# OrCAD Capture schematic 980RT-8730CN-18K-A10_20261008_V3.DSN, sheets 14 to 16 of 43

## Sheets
14 P0041_S4_DUT1: size Custom
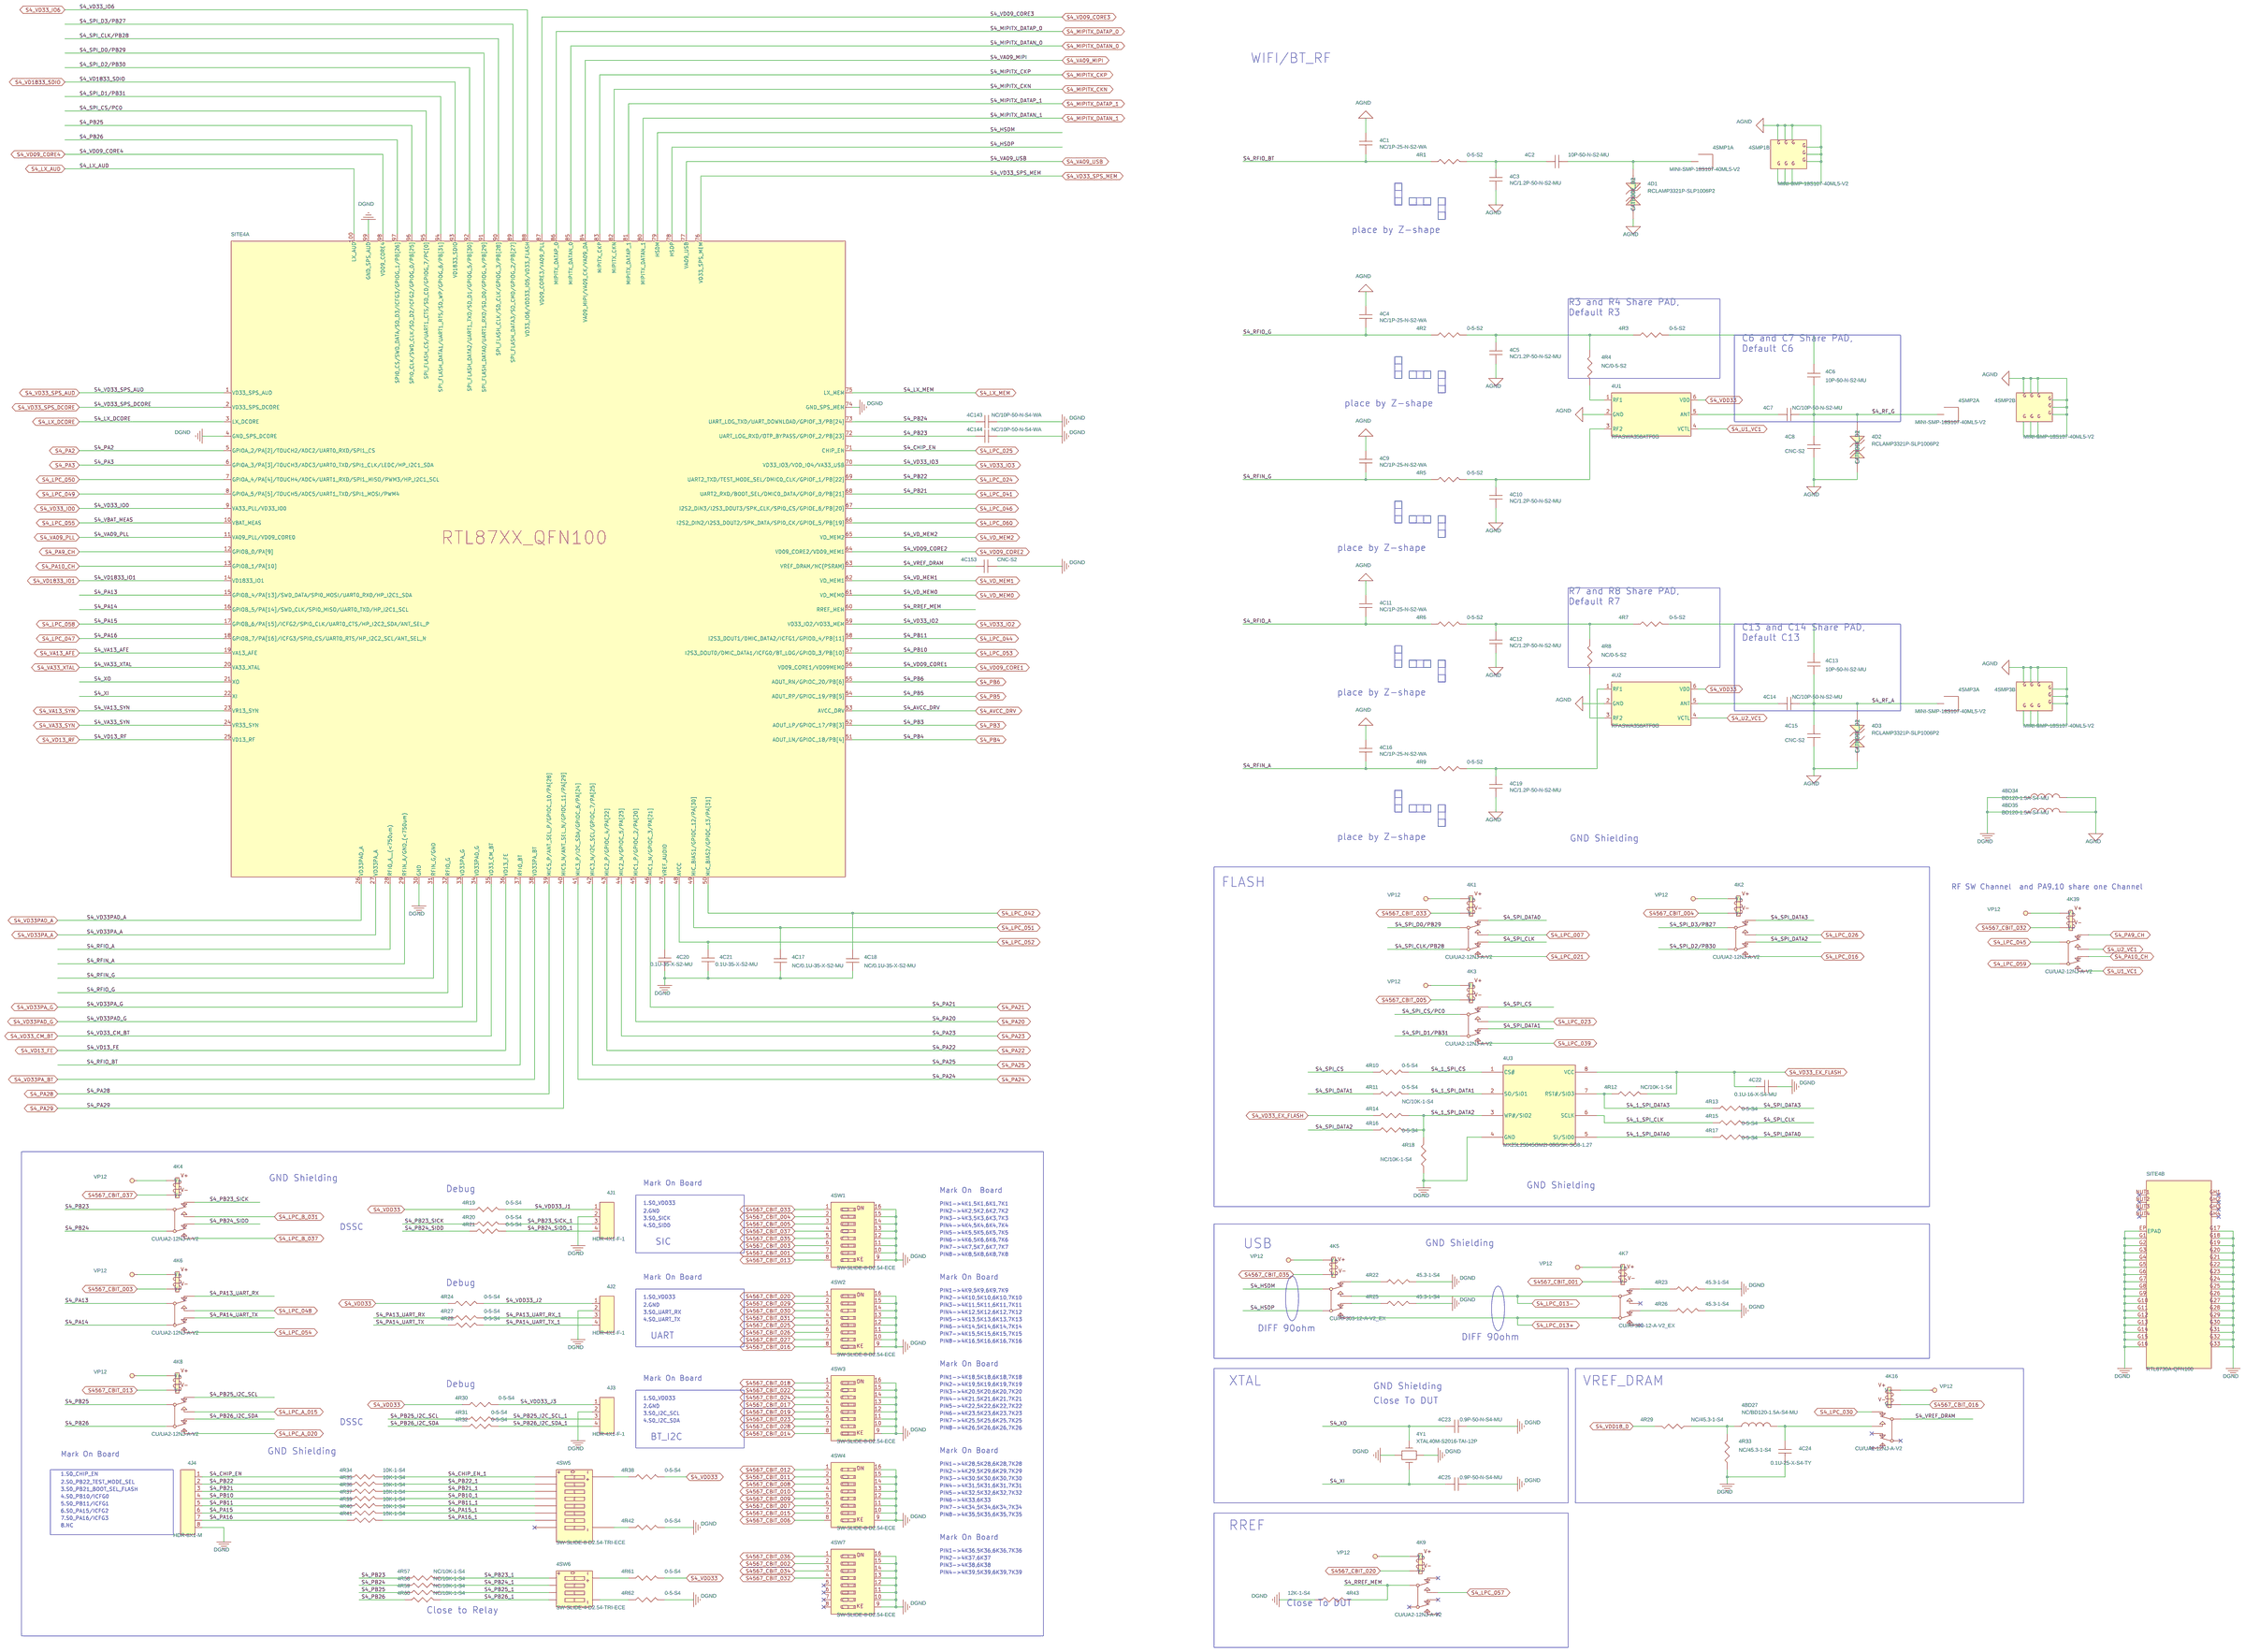
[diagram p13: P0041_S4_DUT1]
15 P0042_S4_Function-test: size A3
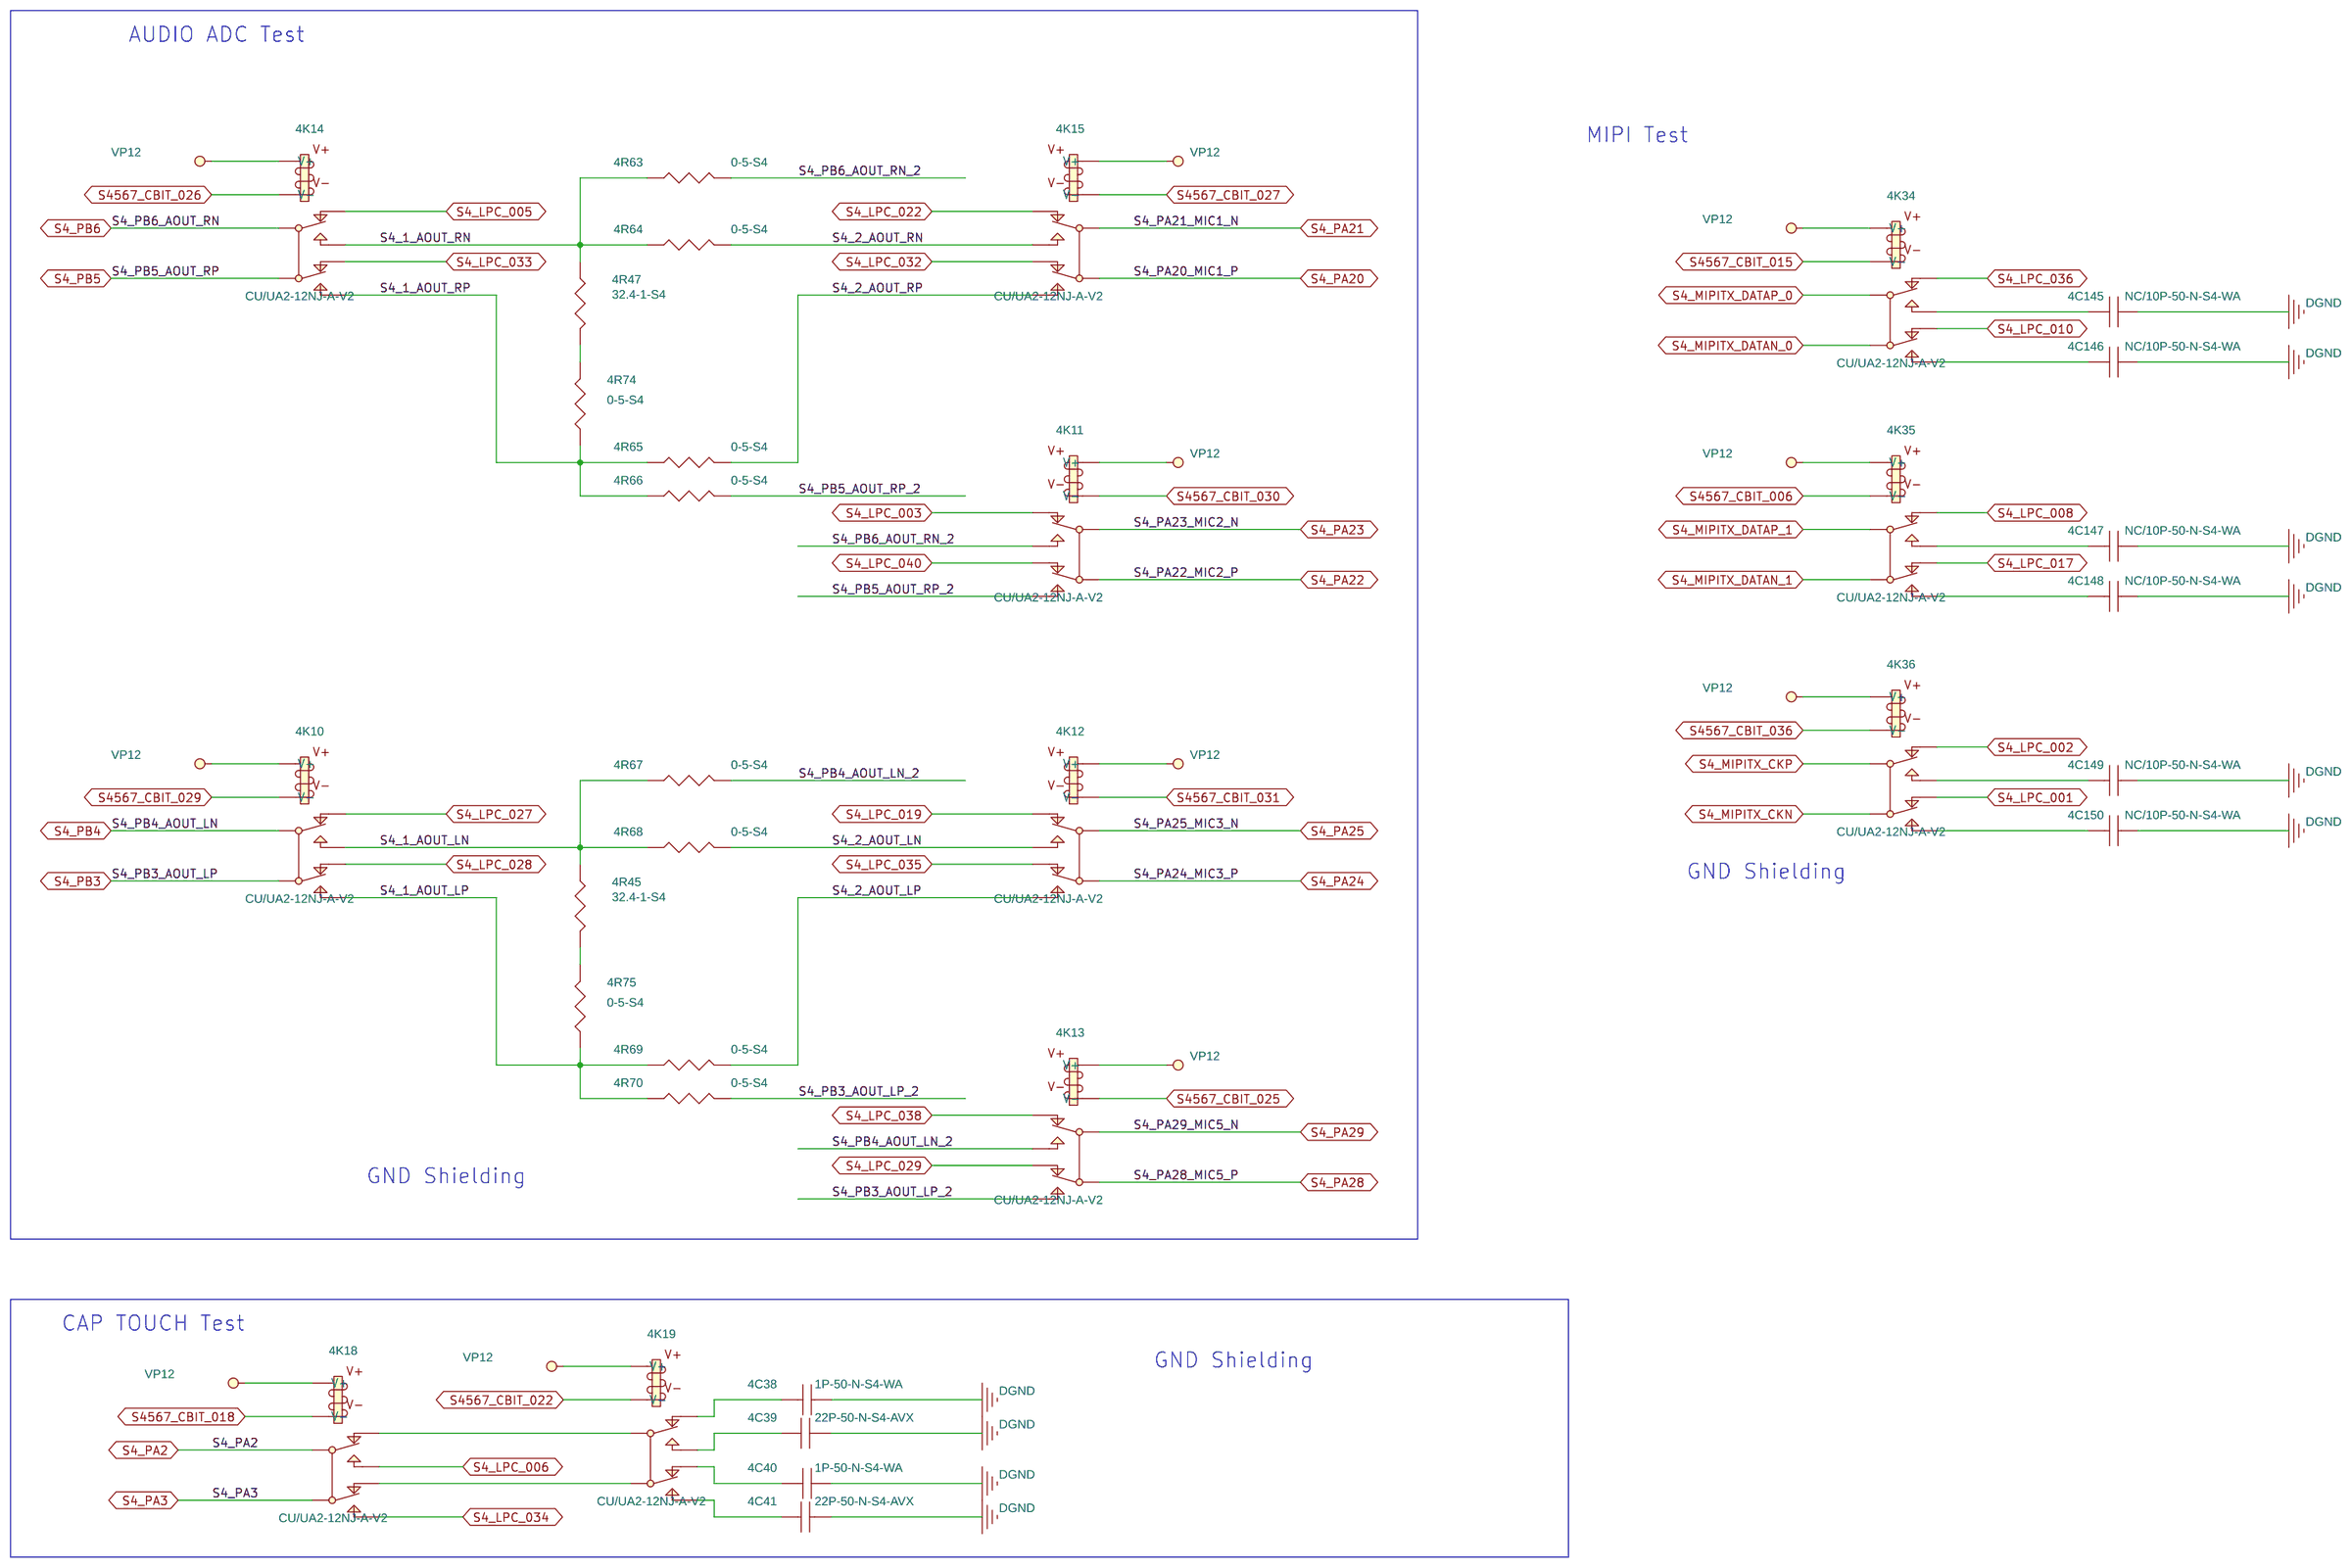
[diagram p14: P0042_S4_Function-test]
16 P0043_S4_Power: size A1
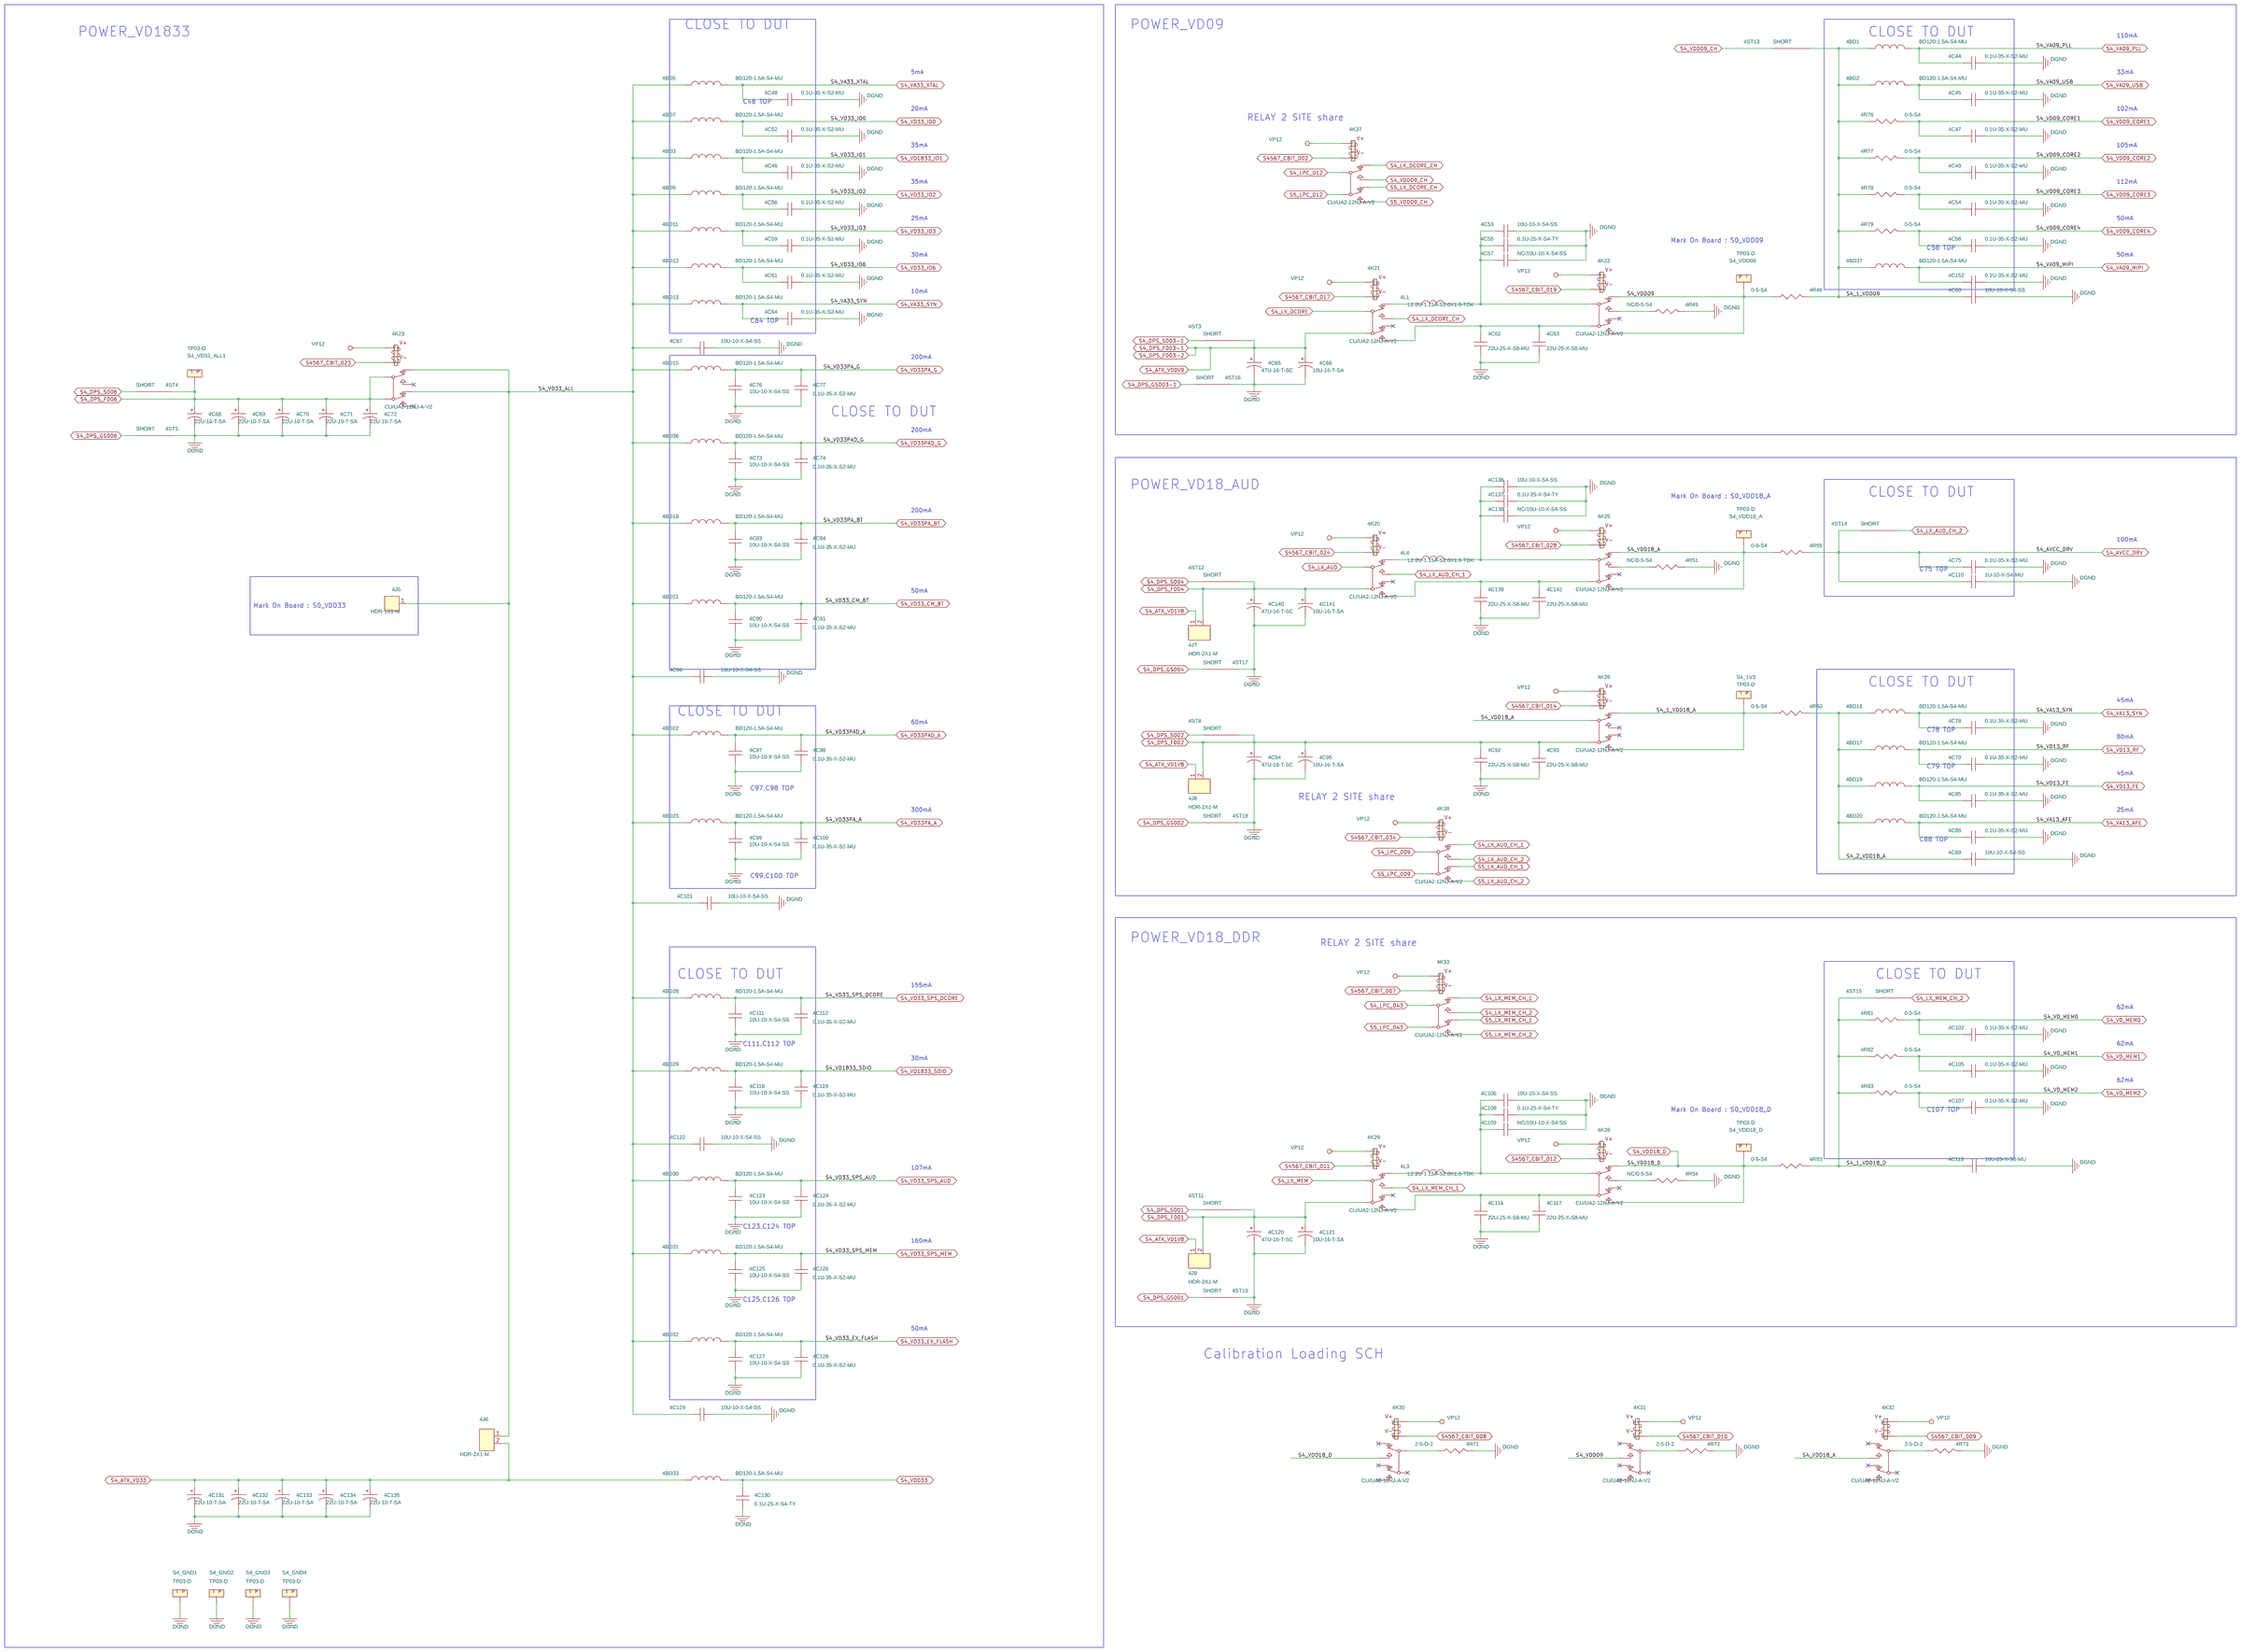
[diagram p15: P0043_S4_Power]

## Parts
sheet P0041_S4_DUT1
4BD27  NC/BD120-1.5A-S4-MU  [FB0402]
4BD34  BD120-1.5A-S4-MU  [FB0402]
4BD35  BD120-1.5A-S4-MU  [FB0402]
4C1  NC/1P-25-N-S2-WA  [C0201]
4C2  10P-50-N-S2-MU  [C0201]
4C3  NC/1.2P-50-N-S2-MU  [C0201]
4C4  NC/1P-25-N-S2-WA  [C0201]
4C5  NC/1.2P-50-N-S2-MU  [C0201]
4C6  10P-50-N-S2-MU  [C0201]
4C7  NC/10P-50-N-S2-MU  [C0201]
4C8  CNC-S2  [C0201]
4C9  NC/1P-25-N-S2-WA  [C0201]
4C10  NC/1.2P-50-N-S2-MU  [C0201]
4C11  NC/1P-25-N-S2-WA  [C0201]
4C12  NC/1.2P-50-N-S2-MU  [C0201]
4C13  10P-50-N-S2-MU  [C0201]
4C14  NC/10P-50-N-S2-MU  [C0201]
4C15  CNC-S2  [C0201]
4C16  NC/1P-25-N-S2-WA  [C0201]
4C17  NC/0.1U-35-X-S2-MU  [C0201]
4C18  NC/0.1U-35-X-S2-MU  [C0201]
4C19  NC/1.2P-50-N-S2-MU  [C0201]
4C20  0.1U-35-X-S2-MU  [C0201]
4C21  0.1U-35-X-S2-MU  [C0201]
4C22  0.1U-16-X-S4-MU  [C0402]
4C23  0.9P-50-N-S4-MU  [C0402]
4C24  0.1U-25-X-S4-TY  [C0402]
4C25  0.9P-50-N-S4-MU  [C0402]
4C143  NC/10P-50-N-S4-WA  [C0402]
4C144  NC/10P-50-N-S4-WA  [C0402]
4C153  CNC-S2  [C0201]
4D1  RCLAMP3321P-SLP1006P2  [DIODE_1X0P6MM]
4D2  RCLAMP3321P-SLP1006P2  [DIODE_1X0P6MM]
4D3  RCLAMP3321P-SLP1006P2  [DIODE_1X0P6MM]
4J1  HDR-4X1-F-1  [CONN_4X1_2P54MM_FL10P5MM]
4J2  HDR-4X1-F-1  [CONN_4X1_2P54MM_FL10P5MM]
4J3  HDR-4X1-F-1  [CONN_4X1_2P54MM_FL10P5MM]
4J4  HDR-8X1-M  [JP_8P_100]
4K1  CU/UA2-12NJ-A-V2  [RL_NECUA2_12V_V2]
4K2  CU/UA2-12NJ-A-V2  [RL_NECUA2_12V_V2]
4K3  CU/UA2-12NJ-A-V2  [RL_NECUA2_12V_V2]
4K4  CU/UA2-12NJ-A-V2  [RL_NECUA2_12V_V2]
4K5  CU/RF303-12-A-V2_EX  [RL_RF303_12V_V2]
4K6  CU/UA2-12NJ-A-V2  [RL_NECUA2_12V_V2]
4K7  CU/RF303-12-A-V2_EX  [RL_RF303_12V_V2]
4K8  CU/UA2-12NJ-A-V2  [RL_NECUA2_12V_V2]
4K9  CU/UA2-12NJ-A-V2  [RL_NECUA2_12V_V2]
4K16  CU/UA2-12NJ-A-V2  [RL_NECUA2_12V_V2]
4K39  CU/UA2-12NJ-A-V2  [RL_NECUA2_12V_V2]
4R1  0-5-S2  [R0201]
4R2  0-5-S2  [R0201]
4R3  0-5-S2  [R0201]
4R4  NC/0-5-S2  [R0201]
4R5  0-5-S2  [R0201]
4R6  0-5-S2  [R0201]
4R7  0-5-S2  [R0201]
4R8  NC/0-5-S2  [R0201]
4R9  0-5-S2  [R0201]
4R10  0-5-S4  [R0402]
4R11  0-5-S4  [R0402]
4R12  NC/10K-1-S4  [R0402]
4R13  0-5-S4  [R0402]
4R14  NC/10K-1-S4  [R0402]
4R15  0-5-S4  [R0402]
4R16  0-5-S4  [R0402]
4R17  0-5-S4  [R0402]
4R18  NC/10K-1-S4  [R0402]
4R19  0-5-S4  [R0402]
4R20  0-5-S4  [R0402]
4R21  0-5-S4  [R0402]
4R22  45.3-1-S4  [R0402]
4R23  45.3-1-S4  [R0402]
4R24  0-5-S4  [R0402]
4R25  45.3-1-S4  [R0402]
4R26  45.3-1-S4  [R0402]
4R27  0-5-S4  [R0402]
4R28  0-5-S4  [R0402]
4R29  NC/45.3-1-S4  [R0402]
4R30  0-5-S4  [R0402]
4R31  0-5-S4  [R0402]
4R32  0-5-S4  [R0402]
4R33  NC/45.3-1-S4  [R0402]
4R34  10K-1-S4  [R0402]
4R35  10K-1-S4  [R0402]
4R36  10K-1-S4  [R0402]
4R37  10K-1-S4  [R0402]
4R38  0-5-S4  [R0402]
4R39  10K-1-S4  [R0402]
4R40  10K-1-S4  [R0402]
4R41  10K-1-S4  [R0402]
4R42  0-5-S4  [R0402]
4R43  12K-1-S4  [R0402]
4R57  NC/10K-1-S4  [R0402]
4R58  NC/10K-1-S4  [R0402]
4R59  NC/10K-1-S4  [R0402]
4R60  NC/10K-1-S4  [R0402]
4R61  0-5-S4  [R0402]
4R62  0-5-S4  [R0402]
4SMP1  MINI-SMP-18S107-40ML5-V2  [CONN_SMP_18S107]  (sections A,B)
4SMP2  MINI-SMP-18S107-40ML5-V2  [CONN_SMP_18S107]  (sections A,B)
4SMP3  MINI-SMP-18S107-40ML5-V2  [CONN_SMP_18S107]  (sections A,B)
4SW1  SW-SLIDE-8-D2.54-ECE  [SW_DIPX8_16P_H5MM]
4SW2  SW-SLIDE-8-D2.54-ECE  [SW_DIPX8_16P_H5MM]
4SW3  SW-SLIDE-8-D2.54-ECE  [SW_DIPX8_16P_H5MM]
4SW4  SW-SLIDE-8-D2.54-ECE  [SW_DIPX8_16P_H5MM]
4SW5  SW-SLIDE-8-D2.54-TRI-ECE  [SW_DIPX8P_2P54_MM_V2]
4SW6  SW-SLIDE-4-D2.54-TRI-ECE  [SW_DIPX4P_2P54MM_ETD]
4SW7  SW-SLIDE-8-D2.54-ECE  [SW_DIPX8_16P_H5MM]
4U1  RFASWA358ATF0G  [RF_SW_GW2159_6P]
4U2  RFASWA358ATF0G  [RF_SW_GW2159_6P]
4U3  MX25L25645GM2I-08G/SK-SO8-1.27  [SK_SO8_1P27MM_LOTES]
4Y1  XTAL40M-S2016-TAI-12P  [XTAL_2X1P6MM_4P_0P8MM]
SITE4  RTL8730A-QFN100  [SK_QFN100P_0P35MM_MJC_L8730A]  (sections A,B)
sheet P0042_S4_Function-test
4C38  1P-50-N-S4-WA  [C0402]
4C39  22P-50-N-S4-AVX  [C0402]
4C40  1P-50-N-S4-WA  [C0402]
4C41  22P-50-N-S4-AVX  [C0402]
4C145  NC/10P-50-N-S4-WA  [C0402]
4C146  NC/10P-50-N-S4-WA  [C0402]
4C147  NC/10P-50-N-S4-WA  [C0402]
4C148  NC/10P-50-N-S4-WA  [C0402]
4C149  NC/10P-50-N-S4-WA  [C0402]
4C150  NC/10P-50-N-S4-WA  [C0402]
4K10  CU/UA2-12NJ-A-V2  [RL_NECUA2_12V_V2]
4K11  CU/UA2-12NJ-A-V2  [RL_NECUA2_12V_V2]
4K12  CU/UA2-12NJ-A-V2  [RL_NECUA2_12V_V2]
4K13  CU/UA2-12NJ-A-V2  [RL_NECUA2_12V_V2]
4K14  CU/UA2-12NJ-A-V2  [RL_NECUA2_12V_V2]
4K15  CU/UA2-12NJ-A-V2  [RL_NECUA2_12V_V2]
4K18  CU/UA2-12NJ-A-V2  [RL_NECUA2_12V_V2]
4K19  CU/UA2-12NJ-A-V2  [RL_NECUA2_12V_V2]
4K34  CU/UA2-12NJ-A-V2  [RL_NECUA2_12V_V2]
4K35  CU/UA2-12NJ-A-V2  [RL_NECUA2_12V_V2]
4K36  CU/UA2-12NJ-A-V2  [RL_NECUA2_12V_V2]
4R45  32.4-1-S4  [R0402]
4R47  32.4-1-S4  [R0402]
4R63  0-5-S4  [R0402]
4R64  0-5-S4  [R0402]
4R65  0-5-S4  [R0402]
4R66  0-5-S4  [R0402]
4R67  0-5-S4  [R0402]
4R68  0-5-S4  [R0402]
4R69  0-5-S4  [R0402]
4R70  0-5-S4  [R0402]
4R74  0-5-S4  [R0402]
4R75  0-5-S4  [R0402]
sheet P0043_S4_Power
4BD1  BD120-1.5A-S4-MU  [FB0402]
4BD2  BD120-1.5A-S4-MU  [FB0402]
4BD3  BD120-1.5A-S4-MU  [FB0402]
4BD5  BD120-1.5A-S4-MU  [FB0402]
4BD7  BD120-1.5A-S4-MU  [FB0402]
4BD9  BD120-1.5A-S4-MU  [FB0402]
4BD11  BD120-1.5A-S4-MU  [FB0402]
4BD12  BD120-1.5A-S4-MU  [FB0402]
4BD13  BD120-1.5A-S4-MU  [FB0402]
4BD15  BD120-1.5A-S4-MU  [FB0402]
4BD16  BD120-1.5A-S4-MU  [FB0402]
4BD17  BD120-1.5A-S4-MU  [FB0402]
4BD18  BD120-1.5A-S4-MU  [FB0402]
4BD19  BD120-1.5A-S4-MU  [FB0402]
4BD20  BD120-1.5A-S4-MU  [FB0402]
4BD21  BD120-1.5A-S4-MU  [FB0402]
4BD22  BD120-1.5A-S4-MU  [FB0402]
4BD23  BD120-1.5A-S4-MU  [FB0402]
4BD28  BD120-1.5A-S4-MU  [FB0402]
4BD29  BD120-1.5A-S4-MU  [FB0402]
4BD30  BD120-1.5A-S4-MU  [FB0402]
4BD31  BD120-1.5A-S4-MU  [FB0402]
4BD32  BD120-1.5A-S4-MU  [FB0402]
4BD33  BD120-1.5A-S4-MU  [FB0402]
4BD36  BD120-1.5A-S4-MU  [FB0402]
4BD37  BD120-1.5A-S4-MU  [FB0402]
4C44  0.1U-35-X-S2-MU  [C0201]
4C45  0.1U-35-X-S2-MU  [C0201]
4C46  0.1U-35-X-S2-MU  [C0201]
4C47  0.1U-35-X-S2-MU  [C0201]
4C48  0.1U-35-X-S2-MU  [C0201]
4C49  0.1U-35-X-S2-MU  [C0201]
4C52  0.1U-35-X-S2-MU  [C0201]
4C53  10U-10-X-S4-SS  [C0402]
4C54  0.1U-35-X-S2-MU  [C0201]
4C55  0.1U-25-X-S4-TY  [C0402]
4C56  0.1U-35-X-S2-MU  [C0201]
4C57  NC/10U-10-X-S4-SS  [C0402]
4C58  0.1U-35-X-S2-MU  [C0201]
4C59  0.1U-35-X-S2-MU  [C0201]
4C60  10U-10-X-S4-SS  [C0402]
4C61  0.1U-35-X-S2-MU  [C0201]
4C62  22U-25-X-S8-MU  [C0805]
4C63  22U-25-X-S8-MU  [C0805]
4C64  0.1U-35-X-S2-MU  [C0201]
4C65  47U-16-T-SC  [CODE_C]
4C66  10U-16-T-SA  [CODE_A]
4C67  10U-10-X-S4-SS  [C0402]
4C68  22U-10-T-SA  [CODE_A]
4C69  22U-10-T-SA  [CODE_A]
4C70  22U-10-T-SA  [CODE_A]
4C71  22U-10-T-SA  [CODE_A]
4C72  22U-10-T-SA  [CODE_A]
4C73  10U-10-X-S4-SS  [C0402]
4C74  0.1U-35-X-S2-MU  [C0201]
4C75  0.1U-35-X-S2-MU  [C0201]
4C76  10U-10-X-S4-SS  [C0402]
4C77  0.1U-35-X-S2-MU  [C0201]
4C78  0.1U-35-X-S2-MU  [C0201]
4C79  0.1U-35-X-S2-MU  [C0201]
4C83  10U-10-X-S4-SS  [C0402]
4C84  0.1U-35-X-S2-MU  [C0201]
4C85  0.1U-35-X-S2-MU  [C0201]
4C88  0.1U-35-X-S2-MU  [C0201]
4C89  10U-10-X-S4-SS  [C0402]
4C90  10U-10-X-S4-SS  [C0402]
4C91  0.1U-35-X-S2-MU  [C0201]
4C92  22U-25-X-S8-MU  [C0805]
4C93  22U-25-X-S8-MU  [C0805]
4C94  47U-16-T-SC  [CODE_C]
4C95  10U-16-T-SA  [CODE_A]
4C96  10U-10-X-S4-SS  [C0402]
4C97  10U-10-X-S4-SS  [C0402]
4C98  0.1U-35-X-S2-MU  [C0201]
4C99  10U-10-X-S4-SS  [C0402]
4C100  0.1U-35-X-S2-MU  [C0201]
4C101  10U-10-X-S4-SS  [C0402]
4C102  0.1U-35-X-S2-MU  [C0201]
4C105  0.1U-35-X-S2-MU  [C0201]
4C106  10U-10-X-S4-SS  [C0402]
4C107  0.1U-35-X-S2-MU  [C0201]
4C108  0.1U-25-X-S4-TY  [C0402]
4C109  NC/10U-10-X-S4-SS  [C0402]
4C110  1U-10-X-S4-MU  [C0402]
4C111  10U-10-X-S4-SS  [C0402]
4C112  0.1U-35-X-S2-MU  [C0201]
4C113  10U-25-X-S6-MU  [C0603]
4C116  22U-25-X-S8-MU  [C0805]
4C117  22U-25-X-S8-MU  [C0805]
4C118  10U-10-X-S4-SS  [C0402]
4C119  0.1U-35-X-S2-MU  [C0201]
4C120  47U-16-T-SC  [CODE_C]
4C121  10U-16-T-SA  [CODE_A]
4C122  10U-10-X-S4-SS  [C0402]
4C123  10U-10-X-S4-SS  [C0402]
4C124  0.1U-35-X-S2-MU  [C0201]
4C125  10U-10-X-S4-SS  [C0402]
4C126  0.1U-35-X-S2-MU  [C0201]
4C127  10U-10-X-S4-SS  [C0402]
4C128  0.1U-35-X-S2-MU  [C0201]
4C129  10U-10-X-S4-SS  [C0402]
4C130  0.1U-25-X-S4-TY  [C0402]
4C131  22U-10-T-SA  [CODE_A]
4C132  22U-10-T-SA  [CODE_A]
4C133  22U-10-T-SA  [CODE_A]
4C134  22U-10-T-SA  [CODE_A]
4C135  22U-10-T-SA  [CODE_A]
4C136  10U-10-X-S4-SS  [C0402]
4C137  0.1U-25-X-S4-TY  [C0402]
4C138  NC/10U-10-X-S4-SS  [C0402]
4C139  22U-25-X-S8-MU  [C0805]
4C140  47U-16-T-SC  [CODE_C]
4C141  10U-16-T-SA  [CODE_A]
4C142  22U-25-X-S8-MU  [C0805]
4C152  0.1U-35-X-S2-MU  [C0201]
4J5  HDR-1X1-M  [JP_1P_RD070_040]
4J6  HDR-2X1-M  [JP_2P_100]
4J7  HDR-2X1-M  [JP_2P_100]
4J8  HDR-2X1-M  [JP_2P_100]
4J9  HDR-2X1-M  [JP_2P_100]
4K20  CU/UA2-12NJ-A-V2  [RL_NECUA2_12V_V2]
4K21  CU/UA2-12NJ-A-V2  [RL_NECUA2_12V_V2]
4K22  CU/UA2-12NJ-A-V2  [RL_NECUA2_12V_V2]
4K23  CU/UA2-12NJ-A-V2  [RL_NECUA2_12V_V2]
4K25  CU/UA2-12NJ-A-V2  [RL_NECUA2_12V_V2]
4K26  CU/UA2-12NJ-A-V2  [RL_NECUA2_12V_V2]
4K28  CU/UA2-12NJ-A-V2  [RL_NECUA2_12V_V2]
4K29  CU/UA2-12NJ-A-V2  [RL_NECUA2_12V_V2]
4K30  CU/UA2-12NJ-A-V2  [RL_NECUA2_12V_V2]
4K31  CU/UA2-12NJ-A-V2  [RL_NECUA2_12V_V2]
4K32  CU/UA2-12NJ-A-V2  [RL_NECUA2_12V_V2]
4K33  CU/UA2-12NJ-A-V2  [RL_NECUA2_12V_V2]
4K37  CU/UA2-12NJ-A-V2  [RL_NECUA2_12V_V2]
4K38  CU/UA2-12NJ-A-V2  [RL_NECUA2_12V_V2]
4L1  L2.2U-1.15A-S2.0X1.6-TDK  [IND_VL252012E]
4L3  L2.2U-1.15A-S2.0X1.6-TDK  [IND_VL252012E]
4L4  L2.2U-1.15A-S2.0X1.6-TDK  [IND_VL252012E]
4R48  0-5-S4  [R0402]
4R49  NC/0-5-S4  [R0402]
4R50  0-5-S4  [R0402]
4R51  NC/0-5-S4  [R0402]
4R53  0-5-S4  [R0402]
4R54  NC/0-5-S4  [R0402]
4R55  0-5-S4  [R0402]
4R71  2-5-D-2  [RC02W_27MM]
4R72  2-5-D-2  [RC02W_27MM]
4R73  2-5-D-2  [RC02W_27MM]
4R76  0-5-S4  [R0402]
4R77  0-5-S4  [R0402]
4R78  0-5-S4  [R0402]
4R79  0-5-S4  [R0402]
4R81  0-5-S4  [R0402]
4R82  0-5-S4  [R0402]
4R83  0-5-S4  [R0402]
4ST3  SHORT  [DEFAULT_SHORT_SMALL]
4ST4  SHORT  [DEFAULT_SHORT_SMALL]
4ST5  SHORT  [DEFAULT_SHORT_SMALL]
4ST8  SHORT  [DEFAULT_SHORT_SMALL]
4ST11  SHORT  [DEFAULT_SHORT_SMALL]
4ST12  SHORT  [DEFAULT_SHORT_SMALL]
4ST13  SHORT  [DEFAULT_SHORT_SMALL]
4ST14  SHORT  [DEFAULT_SHORT_SMALL]
4ST15  SHORT  [DEFAULT_SHORT_SMALL]
4ST16  SHORT  [DEFAULT_SHORT_SMALL]
4ST17  SHORT  [DEFAULT_SHORT_SMALL]
4ST18  SHORT  [DEFAULT_SHORT_SMALL]
4ST19  SHORT  [DEFAULT_SHORT_SMALL]
S4_1V3  TP03-D  [TP_060_040]
S4_GND1  TP03-D  [TP_060_040]
S4_GND2  TP03-D  [TP_060_040]
S4_GND3  TP03-D  [TP_060_040]
S4_GND4  TP03-D  [TP_060_040]
S4_VD33_ALL1  TP03-D  [TP_060_040]
S4_VDD09  TP03-D  [TP_060_040]
S4_VDD18_A  TP03-D  [TP_060_040]
S4_VDD18_D  TP03-D  [TP_060_040]

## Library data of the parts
4BD27 = BD120-1.5A-S4-MU: KAIROSNAME: BD27
4BD34 = BD120-1.5A-S4-MU: KAIROSNAME: BD34
4BD35 = BD120-1.5A-S4-MU: KAIROSNAME: BD35
4C1 4C4 4C9 4C11 4C16 = 1P-25-N-S2-WA
4C2 4C6 4C7 4C13 4C14 = 10P-50-N-S2-MU
4C3 4C5 4C10 4C12 4C19 = 1.2P-50-N-S2-MU
4C8 4C15 = CNC-S4
4C17 4C18 4C46 = 0.1U-35-X-S2-MU: KAIROSNAME: C46
4C20 4C21 4C98 = 0.1U-35-X-S2-MU: KAIROSNAME: C98
4C22 = 0.1U-16-X-S4: KAIROSNAME: C22
4C23 = 10P-50-N-S4-MU-1: KAIROSNAME: C23
4C24 = 0.1U-25-X-S4-TY: KAIROSNAME: C24
4C25 = 10P-50-N-S4-MU-1: KAIROSNAME: C25
4C143-4C150 = 10P-50-N-S4-WA
4C48 4C153 = 0.1U-35-X-S2-MU: KAIROSNAME: C48
4D1 = RCLAMP3321P-SLP1006P2: KAIROSNAME: D1
4D2 = RCLAMP3321P-SLP1006P2: KAIROSNAME: D2
4D3 = RCLAMP3321P-SLP1006P2: KAIROSNAME: D3
4J1-4J3 = HDR-4X1-F-1
4J4 = HDR-8X1-M: KAIROSNAME: J4
4K1 4K39 = CU_UA2-12NJ-A-V2: KAIROSNAME: K1
4K2 4K16 = CU_UA2-12NJ-A-V2: KAIROSNAME: K2
4K3 = CU_UA2-12NJ-A-V2: KAIROSNAME: K3
4K4 = CU_UA2-12NJ-A-V2: KAIROSNAME: K4
4K5 = CU_RF303-12-A-V2_EX: KAIROSNAME: K5
4K6 = CU_UA2-12NJ-A-V2: KAIROSNAME: K6
4K7 = CU_RF303-12-A-V2_EX: KAIROSNAME: K7
4K8 = CU_UA2-12NJ-A-V2: KAIROSNAME: K8
4K9 = CU_UA2-12NJ-A-V2: KAIROSNAME: K9
4R1-4R9 = 0-5-S2
4R10 = 0-5-S4: KAIROSNAME: R10
4R11 = 0-5-S4: KAIROSNAME: R11
4R12 = 10K-1-S4: KAIROSNAME: R12
4R13 = 0-5-S4: KAIROSNAME: R13
4R14 = 10K-1-S4: KAIROSNAME: R14
4R15 = 0-5-S4: KAIROSNAME: R15
4R16 = 0-5-S4: KAIROSNAME: R16
4R17 = 0-5-S4: KAIROSNAME: R17
4R18 = 10K-1-S4: KAIROSNAME: R18
4R19 = 0-5-S4: KAIROSNAME: R19
4R20 = 0-5-S4: KAIROSNAME: R20
4R21 = 0-5-S4: KAIROSNAME: R21
4R22 = 45.3-1-S4: KAIROSNAME: R22
4R23 = 45.3-1-S4: KAIROSNAME: R23
4R24 = 0-5-S4: KAIROSNAME: R24
4R25 = 45.3-1-S4: KAIROSNAME: R25
4R26 = 45.3-1-S4: KAIROSNAME: R26
4R27 = 0-5-S4: KAIROSNAME: R27
4R28 = 0-5-S4: KAIROSNAME: R28
4R29 = 45.3-1-S4: KAIROSNAME: R29
4R30 = 0-5-S4: KAIROSNAME: R30
4R31 = 0-5-S4: KAIROSNAME: R31
4R32 = 0-5-S4: KAIROSNAME: R32
4R33 = 45.3-1-S4: KAIROSNAME: R33
4R34 = 10K-1-S4: KAIROSNAME: R34
4R35 = 10K-1-S4: KAIROSNAME: R35
4R36 = 10K-1-S4: KAIROSNAME: R36
4R37 = 10K-1-S4: KAIROSNAME: R37
4R38 = 0-5-S4: KAIROSNAME: R38
4R39 = 10K-1-S4: KAIROSNAME: R39
4R40 = 10K-1-S4: KAIROSNAME: R40
4R41 = 10K-1-S4: KAIROSNAME: R41
4R42 = 0-5-S4: KAIROSNAME: R42
4R43 = 12K-1-S4: KAIROSNAME: R43
4R57 = 10K-1-S4: KAIROSNAME: R57
4R58 = 10K-1-S4: KAIROSNAME: R58
4R59 = 10K-1-S4: KAIROSNAME: R59
4R60 = 10K-1-S4: KAIROSNAME: R60
4R61 = 0-5-S4: KAIROSNAME: R61
4R62 = 0-5-S4: KAIROSNAME: R62
4SMP1 = MINI-SMP-18S107-40ML5-V2: KAIROSNAME: SMP1A
4SMP2 = MINI-SMP-18S107-40ML5-V2: KAIROSNAME: SMP2A
4SMP3 = MINI-SMP-18S107-40ML5-V2: KAIROSNAME: SMP3A
4SW1-4SW4 4SW7 = SW-SLIDE-8-D2.54-ECE
4SW5 = SW-SLIDE-8-D2.54-TRI-ECE
4SW6 = SW-SLIDE-4-D2.54-TRI-ECE
4U1 4U2 = RFASWA358ATF0G
4U3 = MX25R6435FM2IL0-SOP8: KAIROSNAME: U3
4Y1 = XTAL40M-S2016-TAI-12P: KAIROSNAME: Y1
SITE4 = RTL8730A-QFN100
4C38 = 10P-50-N-S4-MU-1: KAIROSNAME: C38
4C39 = 33P-50-N-S4-WA: KAIROSNAME: C39
4C40 = 10P-50-N-S4-MU-1: KAIROSNAME: C40
4C41 = 33P-50-N-S4-WA: KAIROSNAME: C41
4K10 = CU_UA2-12NJ-A-V2: KAIROSNAME: K10
4K11 = CU_UA2-12NJ-A-V2: KAIROSNAME: K11
4K12 = CU_UA2-12NJ-A-V2: KAIROSNAME: K12
4K13 = CU_UA2-12NJ-A-V2: KAIROSNAME: K13
4K14 = CU_UA2-12NJ-A-V2: KAIROSNAME: K14
4K15 4K34-4K36 = CU_UA2-12NJ-A-V2: KAIROSNAME: K15
4K18 = CU_UA2-12NJ-A-V2: KAIROSNAME: K18
4K19 = CU_UA2-12NJ-A-V2: KAIROSNAME: K19
4R45 = 32.4-1-S4: KAIROSNAME: R45
4R47 = 32.4-1-S4: KAIROSNAME: R47
4R63 = 0-5-S4: KAIROSNAME: R63
4R64 = 0-5-S4: KAIROSNAME: R64
4R65 4R74 4R75 = 0-5-S4: KAIROSNAME: R65
4R66 = 0-5-S4: KAIROSNAME: R66
4R67 = 0-5-S4: KAIROSNAME: R67
4R68 = 0-5-S4: KAIROSNAME: R68
4R69 = 0-5-S4: KAIROSNAME: R69
4R70 = 0-5-S4: KAIROSNAME: R70
4BD1 = BD120-1.5A-S4-MU: KAIROSNAME: BD1
4BD2 = BD120-1.5A-S4-MU: KAIROSNAME: BD2
4BD3 = BD120-1.5A-S4-MU: KAIROSNAME: BD3
4BD5 = BD120-1.5A-S4-MU: KAIROSNAME: BD5
4BD7 = BD120-1.5A-S4-MU: KAIROSNAME: BD7
4BD9 = BD120-1.5A-S4-MU: KAIROSNAME: BD9
4BD11 = BD120-1.5A-S4-MU: KAIROSNAME: BD11
4BD12 = BD120-1.5A-S4-MU: KAIROSNAME: BD12
4BD13 = BD120-1.5A-S4-MU: KAIROSNAME: BD13
4BD15 4BD36 = BD120-1.5A-S4-MU: KAIROSNAME: BD15
4BD16 = BD120-1.5A-S4-MU: KAIROSNAME: BD16
4BD17 = BD120-1.5A-S4-MU: KAIROSNAME: BD17
4BD18 = BD120-1.5A-S4-MU: KAIROSNAME: BD18
4BD19 = BD120-1.5A-S4-MU: KAIROSNAME: BD19
4BD20 = BD120-1.5A-S4-MU: KAIROSNAME: BD20
4BD21 = BD120-1.5A-S4-MU: KAIROSNAME: BD21
4BD22 = BD120-1.5A-S4-MU: KAIROSNAME: BD22
4BD23 = BD120-1.5A-S4-MU: KAIROSNAME: BD23
4BD28 = BD120-1.5A-S4-MU: KAIROSNAME: BD28
4BD29 = BD120-1.5A-S4-MU: KAIROSNAME: BD29
4BD30 = BD120-1.5A-S4-MU: KAIROSNAME: BD30
4BD31 = BD120-1.5A-S4-MU: KAIROSNAME: BD31
4BD32 = BD120-1.5A-S4-MU: KAIROSNAME: BD32
4BD33 = BD120-1.5A-S4-MU: KAIROSNAME: BD33
4BD37 = BD120-1.5A-S4-MU: KAIROSNAME: BD10
4C44 = 0.1U-35-X-S2-MU: KAIROSNAME: C44
4C45 = 0.1U-35-X-S2-MU: KAIROSNAME: C45
4C47 = 0.1U-35-X-S2-MU: KAIROSNAME: C47
4C49 = 0.1U-35-X-S2-MU: KAIROSNAME: C49
4C52 = 0.1U-35-X-S2-MU: KAIROSNAME: C52
4C53 = 10U-10-X-S4-SS: KAIROSNAME: C53
4C54 = 0.1U-35-X-S2-MU: KAIROSNAME: C54
4C55 = 0.1U-25-X-S4-TY: KAIROSNAME: C55
4C56 = 0.1U-35-X-S2-MU: KAIROSNAME: C56
4C57 = 10U-10-X-S4-SS: KAIROSNAME: C57
4C58 4C152 = 0.1U-35-X-S2-MU: KAIROSNAME: C58
4C59 = 0.1U-35-X-S2-MU: KAIROSNAME: C59
4C60 = 10U-10-X-S4-SS: KAIROSNAME: C60
4C61 = 0.1U-35-X-S2-MU: KAIROSNAME: C61
4C62 = 22U-25-X-S8-MU: KAIROSNAME: C62
4C63 = 22U-25-X-S8-MU: KAIROSNAME: C63
4C64 = 0.1U-35-X-S2-MU: KAIROSNAME: C64
4C65 = 47U-16-T-SC: KAIROSNAME: C65
4C66 = 10U-16-T-SA: KAIROSNAME: C66
4C67 = 10U-10-X-S4-SS: KAIROSNAME: C67
4C68 = 22U-10-T-SA: KAIROSNAME: C68
4C69 = 22U-10-T-SA: KAIROSNAME: C69
4C70 = 22U-10-T-SA: KAIROSNAME: C70
4C71 = 22U-10-T-SA: KAIROSNAME: C71
4C72 = 22U-10-T-SA: KAIROSNAME: C72
4C73 4C76 = 10U-10-X-S4-SS: KAIROSNAME: C76
4C74 4C77 = 0.1U-35-X-S2-MU: KAIROSNAME: C77
4C75 = 0.1U-35-X-S2-MU: KAIROSNAME: C75
4C78 = 0.1U-35-X-S2-MU: KAIROSNAME: C78
4C79 = 0.1U-35-X-S2-MU: KAIROSNAME: C79
4C83 = 10U-10-X-S4-SS: KAIROSNAME: C83
4C84 = 0.1U-35-X-S2-MU: KAIROSNAME: C84
4C85 = 0.1U-35-X-S2-MU: KAIROSNAME: C85
4C88 = 0.1U-35-X-S2-MU: KAIROSNAME: C88
4C89 = 10U-10-X-S4-SS: KAIROSNAME: C89
4C90 = 10U-10-X-S4-SS: KAIROSNAME: C90
4C91 = 0.1U-35-X-S2-MU: KAIROSNAME: C91
4C92 = 22U-25-X-S8-MU: KAIROSNAME: C92
4C93 = 22U-25-X-S8-MU: KAIROSNAME: C93
4C94 = 47U-16-T-SC: KAIROSNAME: C94
4C95 = 10U-16-T-SA: KAIROSNAME: C95
4C96 = 10U-10-X-S4-SS: KAIROSNAME: C96
4C97 = 10U-10-X-S4-SS: KAIROSNAME: C97
4C99 = 10U-10-X-S4-SS: KAIROSNAME: C99
4C100 = 0.1U-35-X-S2-MU: KAIROSNAME: C100
4C101 = 10U-10-X-S4-SS: KAIROSNAME: C101
4C102 = 0.1U-35-X-S2-MU: KAIROSNAME: C102
4C105 = 0.1U-35-X-S2-MU: KAIROSNAME: C105
4C106 = 10U-10-X-S4-SS: KAIROSNAME: C106
4C107 = 0.1U-35-X-S2-MU: KAIROSNAME: C107
4C108 = 0.1U-25-X-S4-TY: KAIROSNAME: C108
4C109 = 10U-10-X-S4-SS: KAIROSNAME: C109
4C110 = 10U-10-X-S4-SS: KAIROSNAME: C110
4C111 = 10U-10-X-S4-SS: KAIROSNAME: C111
4C112 = 0.1U-35-X-S2-MU: KAIROSNAME: C112
4C113 = 10U-25-X-S6-MU: KAIROSNAME: C113
4C116 = 22U-25-X-S8-MU: KAIROSNAME: C116
4C117 = 22U-25-X-S8-MU: KAIROSNAME: C117
4C118 = 10U-10-X-S4-SS: KAIROSNAME: C118
4C119 = 0.1U-35-X-S2-MU: KAIROSNAME: C119
4C120 = 47U-16-T-SC: KAIROSNAME: C120
4C121 = 10U-16-T-SA: KAIROSNAME: C121
4C122 = 10U-10-X-S4-SS: KAIROSNAME: C122
4C123 = 10U-10-X-S4-SS: KAIROSNAME: C123
4C124 = 0.1U-35-X-S2-MU: KAIROSNAME: C124
4C125 = 10U-10-X-S4-SS: KAIROSNAME: C125
4C126 = 0.1U-35-X-S2-MU: KAIROSNAME: C126
4C127 = 10U-10-X-S4-SS: KAIROSNAME: C127
4C128 = 0.1U-35-X-S2-MU: KAIROSNAME: C128
4C129 = 10U-10-X-S4-SS: KAIROSNAME: C129
4C130 = 0.1U-25-X-S4-TY: KAIROSNAME: C130
4C131 = 22U-10-T-SA: KAIROSNAME: C131
4C132 = 22U-10-T-SA: KAIROSNAME: C132
4C133 = 22U-10-T-SA: KAIROSNAME: C133
4C134 = 22U-10-T-SA: KAIROSNAME: C134
4C135 = 22U-10-T-SA: KAIROSNAME: C135
4C136 = 10U-10-X-S4-SS: KAIROSNAME: C136
4C137 = 0.1U-25-X-S4-TY: KAIROSNAME: C137
4C138 = 10U-10-X-S4-SS: KAIROSNAME: C138
4C139 = 22U-25-X-S8-MU: KAIROSNAME: C139
4C140 = 47U-16-T-SC: KAIROSNAME: C140
4C141 = 10U-16-T-SA: KAIROSNAME: C141
4C142 = 22U-25-X-S8-MU: KAIROSNAME: C142
4J5 = HDR-1X1-M: KAIROSNAME: J5
4J6 = HDR-2X1-M: KAIROSNAME: J6
4J7 = HDR-2X1-M: KAIROSNAME: J7
4J8 = HDR-2X1-M: KAIROSNAME: J8
4J9 = HDR-2X1-M: KAIROSNAME: J9
4K20 = CU_UA2-12NJ-A-V2: KAIROSNAME: K20
4K21 = CU_UA2-12NJ-A-V2: KAIROSNAME: K21
4K22 4K37 4K38 = CU_UA2-12NJ-A-V2: KAIROSNAME: K22
4K23 = CU_UA2-12NJ-A-V2: KAIROSNAME: K23
4K25 = CU_UA2-12NJ-A-V2: KAIROSNAME: K25
4K26 4K33 = CU_UA2-12NJ-A-V2: KAIROSNAME: K26
4K28 4K30-4K32 = CU_UA2-12NJ-A-V2: KAIROSNAME: K28
4K29 = CU_UA2-12NJ-A-V2: KAIROSNAME: K29
4L1 = L2.2U-1.15A-S2.0X1.6-TDK: KAIROSNAME: L1
4L3 = L2.2U-1.15A-S2.0X1.6-TDK: KAIROSNAME: L3
4L4 = L2.2U-1.15A-S2.0X1.6-TDK: KAIROSNAME: L4
4R48 = 0-5-S4: KAIROSNAME: R48
4R49 = 0-5-S4: KAIROSNAME: R49
4R50 = 0-5-S4: KAIROSNAME: R50
4R51 = 0-5-S4: KAIROSNAME: R51
4R53 = 0-5-S4: KAIROSNAME: R53
4R54 = 0-5-S4: KAIROSNAME: R54
4R55 = 0-5-S4: KAIROSNAME: R55
4R71-4R73 = 2-5-D-2
4R76-4R79 4R81-4R83 = 0-5-S4
4ST3 4ST13-4ST15 = SHORT: KAIROSNAME: ST3
4ST4 = SHORT: KAIROSNAME: ST4
4ST5 4ST16-4ST19 = SHORT: KAIROSNAME: ST5
4ST8 = SHORT: KAIROSNAME: ST8
4ST11 = SHORT: KAIROSNAME: ST11
4ST12 = SHORT: KAIROSNAME: ST12
S4_1V3 = TP03-D: KAIROSNAME: S0_TP_VD3
S4_GND1 = TP03-D: KAIROSNAME: S0_GND1
S4_GND2 = TP03-D: KAIROSNAME: S0_GND2
S4_GND3 = TP03-D: KAIROSNAME: S0_GND3
S4_GND4 = TP03-D: KAIROSNAME: S0_GND4
S4_VD33_ALL1 = TP03-D: KAIROSNAME: S0_VD33_ALL1
S4_VDD09 = TP03-D: KAIROSNAME: S0_VDD09
S4_VDD18_A = TP03-D: KAIROSNAME: S0_VDD18_A
S4_VDD18_D = TP03-D: KAIROSNAME: S0_VDD18_D

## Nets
AGND: 4BD34.2 4BD35.2 4C1.1 4C3.2 4C4.1 4C5.2 4C8.2 4C9.1 4C10.2 4C11.1 4C12.2 4C15.2 4C16.1 4C19.2 4D1.2(CATHODE_D2) 4D2.2(CATHODE_D2) 4D3.2(CATHODE_D2) 4SMP1.G1 4SMP1.G2 4SMP1.G3 4SMP1.G4 4SMP1.G5 4SMP1.G6 4SMP1.G7 4SMP1.G8 4SMP1.G9 4SMP2.G1 4SMP2.G2 4SMP2.G3 4SMP2.G4 4SMP2.G5 4SMP2.G6 4SMP2.G7 4SMP2.G8 4SMP2.G9 4SMP3.G1 4SMP3.G2 4SMP3.G3 4SMP3.G4 4SMP3.G5 4SMP3.G6 4SMP3.G7 4SMP3.G8 4SMP3.G9 4U1.2(GND) 4U2.2(GND) ; also on sheet 2 5 8 11 17 20 23
DGND: 4BD34.1 4BD35.1 4C17.1 4C18.1 4C20.2 4C21.2 4C22.2 4C23.1 4C24.2 4C25.1 4C38.1 4C39.2 4C40.1 4C41.2 4C44.2 4C45.2 4C46.2 4C47.2 4C48.2 4C49.2 4C52.2 4C53.2 4C54.2 4C55.2 4C56.2 4C57.2 4C58.2 4C59.2 4C60.2 4C61.2 4C62.2 4C63.2 4C64.2 4C65.2 4C66.2 4C67.2 4C68.2 4C69.2 4C70.2 4C71.2 4C72.2 4C73.2 4C74.2 4C75.2 4C76.2 4C77.2 4C78.2 4C79.2 4C83.2 4C84.2 4C85.2 4C88.2 4C89.2 4C90.2 4C91.2 4C92.2 4C93.2 4C94.2 4C95.2 4C96.2 4C97.2 4C98.2 4C99.2 4C100.2 4C101.2 4C102.2 4C105.2 4C106.2 4C107.2 4C108.2 4C109.2 4C110.2 4C111.2 4C112.2 4C113.1 4C116.2 4C117.2 4C118.2 4C119.2 4C120.2 4C121.2 4C122.2 4C123.2 4C124.2 4C125.2 4C126.2 4C127.2 4C128.2 4C129.2 4C130.2 4C131.2 4C132.2 4C133.2 4C134.2 4C135.2 4C136.2 4C137.2 4C138.2 4C139.2 4C140.2 4C141.2 4C142.2 4C143.1 4C144.1 4C145.1 4C146.1 4C147.1 4C148.1 4C149.1 4C150.1 4C152.2 4C153.2 4J1.2 4J2.2 4J3.2 4J4.8 4R18.1 4R22.2 4R23.2 4R25.2 4R26.2 4R33.1 4R42.2 4R43.2 4R49.2 4R51.2 4R54.2 4R62.2 4R71.2 4R72.2 4R73.2 4ST5.2 4ST16.2 4ST17.2 4ST18.2 4ST19.2 4SW1.9 4SW1.10 4SW1.11 4SW1.12 4SW1.13 4SW1.14 4SW1.15 4SW1.16 4SW2.9 4SW2.10 4SW2.11 4SW2.12 4SW2.13 4SW2.14 4SW2.15 4SW2.16 4SW3.9 4SW3.10 4SW3.11 4SW3.12 4SW3.13 4SW3.14 4SW3.15 4SW3.16 4SW4.9 4SW4.10 4SW4.11 4SW4.12 4SW4.13 4SW4.14 4SW4.15 4SW4.16 4SW7.9 4SW7.10 4SW7.11 4SW7.12 4SW7.13 4SW7.14 4SW7.15 4SW7.16 4U3.4(GND) 4Y1.2 4Y1.4 S4_GND1.1(TP) S4_GND2.1(TP) S4_GND3.1(TP) S4_GND4.1(TP) SITE4.4(GND_SPS_DCORE) SITE4.30(GND) SITE4.74(GND_SPS_MEM) SITE4.99(GND_SPS_AUD) SITE4.EP(EPAD) SITE4.G1 SITE4.G2 SITE4.G3 SITE4.G4 SITE4.G5 SITE4.G6 SITE4.G7 SITE4.G8 SITE4.G9 SITE4.G10 SITE4.G11 SITE4.G12 SITE4.G13 SITE4.G14 SITE4.G15 SITE4.G16 SITE4.G17 SITE4.G18 SITE4.G19 SITE4.G20 SITE4.G21 SITE4.G22 SITE4.G23 SITE4.G24 SITE4.G25 SITE4.G26 SITE4.G27 SITE4.G28 SITE4.G29 SITE4.G30 SITE4.G31 SITE4.G32 SITE4.G33 ; also on sheet 2 3 4 5 6 7 8 9 10 11 12 13 17 18 19 20 21 22 23 24 25 26 27 29 30 32 34 37 39
S4_1_AOUT_LN: 4K10.4 4R45.1 4R67.1 4R68.1
S4_1_AOUT_LP: 4K10.5 4R69.1 4R70.1 4R75.1
S4_1_AOUT_RN: 4K14.4 4R47.1 4R63.1 4R64.1
S4_1_AOUT_RP: 4K14.5 4R65.1 4R66.1 4R74.1
S4_1_SPI_CLK: 4R15.1 4U3.6(SCLK)
S4_1_SPI_CS: 4R10.2 4U3.1(CS#)
S4_1_SPI_DATA0: 4R17.1 4U3.5(SI/SIO0)
S4_1_SPI_DATA1: 4R11.2 4U3.2(SO/SIO1)
S4_1_SPI_DATA2: 4R14.2 4R16.2 4R18.2 4U3.3(WP#/SIO2)
S4_1_SPI_DATA3: 4R12.1 4R13.1 4U3.7(RST#/SIO3)
S4_1_VDD09: 4BD1.1 4BD2.1 4BD37.1 4C60.1 4R48.2 4R76.1 4R77.1 4R78.1 4R79.1 4ST13.2
S4_1_VDD18_A: 4K26.2 4K26.5 4R50.1 S4_1V3.1(TP)
S4_1_VDD18_D: 4C113.2 4R53.2 4R81.1 4R82.1 4R83.1 4ST15.1
S4_2_AOUT_LN: 4K12.4 4R68.2
S4_2_AOUT_LP: 4K12.5 4R69.2
S4_2_AOUT_RN: 4K15.4 4R64.2
S4_2_AOUT_RP: 4K15.5 4R65.2
S4_2_VDD18_A: 4BD16.1 4BD17.1 4BD19.1 4BD20.1 4C89.1 4R50.2
S4_ATX_VD0V9: 4C65.1 4C66.1 4K21.6 4ST3.2 ; also on sheet 27
S4_ATX_VD1V8: 4J7.1 4J8.1 4J9.1 ; also on sheet 27
S4_ATX_VD33: 4BD33.1 4C131.1 4C132.1 4C133.1 4C134.1 4C135.1 4J6.2 ; also on sheet 27
S4_AVCC_DRV: 4C75.1 4C110.1 4R55.2 4ST14.1 SITE4.53(AVCC_DRV)
S4_CHIP_EN_1: 4R34.2 4SW5.1
S4_DPS_F001: 4C120.1 4C121.1 4J9.2 4K29.6 4ST11.2
S4_DPS_F002: 4C92.1 4C93.1 4C94.1 4C95.1 4J8.2 4K26.6 4ST8.2
S4_DPS_F004: 4C140.1 4C141.1 4J7.2 4K20.6 4ST12.2
S4_DPS_F006: 4C68.1 4C69.1 4C70.1 4C71.1 4C72.1 4K23.3 4K23.6 4ST4.2 S4_VD33_ALL1.1(TP)
S4_DPS_GS001: 4ST19.1
S4_DPS_GS002: 4ST18.1
S4_DPS_GS003-1: 4ST16.1
S4_DPS_GS004: 4ST17.1
S4_DPS_GS006: 4ST5.1
S4_DPS_S001: 4ST11.1
S4_DPS_S002: 4ST8.1
S4_DPS_S003-1: 4ST3.1
S4_DPS_S004: 4ST12.1
S4_DPS_S006: 4ST4.1
S4_HSDM: 4K5.8 SITE4.79(HSDM)
S4_HSDP: 4K5.2 SITE4.78(HSDP)
S4_LPC_001: 4K36.7
S4_LPC_002: 4K36.2
S4_LPC_003: 4K11.2
S4_LPC_005: 4K14.2
S4_LPC_006: 4K18.4
S4_LPC_007: 4K1.4
S4_LPC_008: 4K35.2
S4_LPC_009: 4K38.3
S4_LPC_010: 4K34.7
S4_LPC_012: 4K37.3
S4_LPC_013+: 4K5.3 4K7.2
S4_LPC_013-: 4K5.7 4K7.8
S4_LPC_016: 4K2.5
S4_LPC_017: 4K35.7
S4_LPC_019: 4K12.2
S4_LPC_021: 4K1.5
S4_LPC_022: 4K15.2
S4_LPC_023: 4K3.4
S4_LPC_024: 4J4.2 4R35.1 SITE4.69(UART2_TXD/TEST_MODE_SEL/DMIC0_CLK/GPIOF_1/PB[22])
S4_LPC_025: 4J4.1 4R34.1 SITE4.71(CHIP_EN)
S4_LPC_026: 4K2.4
S4_LPC_027: 4K10.2
S4_LPC_028: 4K10.7
S4_LPC_029: 4K13.7
S4_LPC_030: 4K16.2
S4_LPC_032: 4K15.7
S4_LPC_033: 4K14.7
S4_LPC_034: 4K18.5
S4_LPC_035: 4K12.7
S4_LPC_036: 4K34.2
S4_LPC_038: 4K13.2
S4_LPC_039: 4K3.5
S4_LPC_040: 4K11.7
S4_LPC_041: 4J4.3 4R36.1 SITE4.68(UART2_RXD/BOOT_SEL/DMIC0_DATA/GPIOF_0/PB[21])
S4_LPC_042: 4C18.2 SITE4.50(MIC_BIAS2/GPIOC_13/PA[31])
S4_LPC_043: 4K33.3
S4_LPC_044: 4J4.5 4R39.1 SITE4.58(I2S3_DOUT1/DMIC_DATA2/ICFG1/GPIOD_4/PB[11])
S4_LPC_045: 4K39.3
S4_LPC_046: SITE4.67(I2S2_DIN3/I2S3_DOUT3/SPK_CLK/SPI0_CS/GPIOE_6/PB[20])
S4_LPC_047: 4J4.7 4R41.1 SITE4.18(GPIOB_7/PA[16]/ICFG3/SPI0_CS/UART0_RTS/HP_I2C2_SCL/ANT_SEL_N)
S4_LPC_048: 4K6.4
S4_LPC_049: SITE4.8(GPIOA_5/PA[5]/TOUCH5/ADC5/UART1_TXD/SPI1_MOSI/PWM4)
S4_LPC_050: SITE4.7(GPIOA_4/PA[4]/TOUCH4/ADC4/UART1_RXD/SPI1_MISO/PWM3/HP_I2C1_SCL)
S4_LPC_051: 4C17.2 SITE4.49(MIC_BIAS1/GPIOC_12/PA[30])
S4_LPC_052: 4C21.1 SITE4.48(AVCC)
S4_LPC_053: 4J4.4 4R37.1 SITE4.57(I2S3_DOUT0/DMIC_DATA1/ICFG0/BT_LOG/GPIOD_3/PB[10])
S4_LPC_054: 4K6.5
S4_LPC_055: SITE4.10(VBAT_MEAS)
S4_LPC_057: 4K9.4
S4_LPC_058: 4J4.6 4R40.1 SITE4.17(GPIOB_6/PA[15]/ICFG2/SPI0_CLK/UART0_CTS/HP_I2C2_SDA/ANT_SEL_P)
S4_LPC_059: 4K39.6
S4_LPC_060: SITE4.66(I2S2_DIN2/I2S3_DOUT2/SPK_DATA/SPI0_CK/GPIOE_5/PB[19])
S4_LPC_A_015: 4K8.4
S4_LPC_A_020: 4K8.5
S4_LPC_B_031: 4K4.4
S4_LPC_B_037: 4K4.5
S4_LX_AUD: 4K20.3 SITE4.100(LX_AUD)
S4_LX_AUD_CH_1: 4K20.4 4K38.2
S4_LX_AUD_CH_2: 4K38.4 4ST14.2
S4_LX_DCORE: 4K21.3 SITE4.3(LX_DCORE)
S4_LX_DCORE_CH: 4K21.4 4K37.2
S4_LX_MEM: 4K29.3 SITE4.75(LX_MEM)
S4_LX_MEM_CH_1: 4K29.4 4K33.2
S4_LX_MEM_CH_2: 4K33.4 4ST15.2
S4_MIPITX_CKN: 4K36.6 SITE4.82(MIPITX_CKN)
S4_MIPITX_CKP: 4K36.3 SITE4.83(MIPITX_CKP)
S4_MIPITX_DATAN_0: 4K34.6 SITE4.85(MIPITX_DATAN_0)
S4_MIPITX_DATAN_1: 4K35.6 SITE4.80(MIPITX_DATAN_1)
S4_MIPITX_DATAP_0: 4K34.3 SITE4.86(MIPITX_DATAP_0)
S4_MIPITX_DATAP_1: 4K35.3 SITE4.81(MIPITX_DATAP_1)
S4_PA2: 4K18.3 SITE4.5(GPIOA_2/PA[2]/TOUCH2/ADC2/UART0_RXD/SPI1_CS)
S4_PA3: 4K18.6 SITE4.6(GPIOA_3/PA[3]/TOUCH3/ADC3/UART0_TXD/SPI1_CLK/LEDC/HP_I2C1_SDA)
S4_PA9_CH: 4K39.2 SITE4.12(GPIOB_0/PA[9])
S4_PA10_CH: 4K39.7 SITE4.13(GPIOB_1/PA[10])
S4_PA13: 4K6.3 SITE4.15(GPIOB_4/PA[13]/SWD_DATA/SPI0_MOSI/UART0_RXD/HP_I2C1_SDA)
S4_PA13_UART_RX: 4K6.2 4R27.1
S4_PA13_UART_RX_1: 4J2.3 4R27.2
S4_PA14: 4K6.6 SITE4.16(GPIOB_5/PA[14]/SWD_CLK/SPI0_MISO/UART0_TXD/HP_I2C1_SCL)
S4_PA14_UART_TX: 4K6.7 4R28.1
S4_PA14_UART_TX_1: 4J2.4 4R28.2
S4_PA15_1: 4R40.2 4SW5.6
S4_PA16_1: 4R41.2 4SW5.7
S4_PA20: 4K15.6 SITE4.45(MIC1_P/GPIOC_2/PA[20])
S4_PA21: 4K15.3 SITE4.46(MIC1_N/GPIOC_3/PA[21])
S4_PA22: 4K11.6 SITE4.43(MIC2_P/GPIOC_4/PA[22])
S4_PA23: 4K11.3 SITE4.44(MIC2_N/GPIOC_5/PA[23])
S4_PA24: 4K12.6 SITE4.41(MIC3_P/I2C_SDA/GPIOC_6/PA[24])
S4_PA25: 4K12.3 SITE4.42(MIC3_N/I2C_SCL/GPIOC_7/PA[25])
S4_PA28: 4K13.6 SITE4.39(MIC5_P/ANT_SEL_P/GPIOC_10/PA[28])
S4_PA29: 4K13.3 SITE4.40(MIC5_N/ANT_SEL_N/GPIOC_11/PA[29])
S4_PB3: 4K10.6 SITE4.52(AOUT_LP/GPIOC_17/PB[3])
S4_PB3_AOUT_LP_2: 4K13.5 4R70.2
S4_PB4: 4K10.3 SITE4.51(AOUT_LN/GPIOC_18/PB[4])
S4_PB4_AOUT_LN_2: 4K13.4 4R67.2
S4_PB5: 4K14.6 SITE4.54(AOUT_RP/GPIOC_19/PB[5])
S4_PB5_AOUT_RP_2: 4K11.5 4R66.2
S4_PB6: 4K14.3 SITE4.55(AOUT_RN/GPIOC_20/PB[6])
S4_PB6_AOUT_RN_2: 4K11.4 4R63.2
S4_PB10_1: 4R37.2 4SW5.4
S4_PB11_1: 4R39.2 4SW5.5
S4_PB21_1: 4R36.2 4SW5.3
S4_PB22_1: 4R35.2 4SW5.2
S4_PB23: 4C144.2 4K4.3 4R57.1 SITE4.72(UART_LOG_RXD/OTP_BYPASS/GPIOF_2/PB[23])
S4_PB23_1: 4R57.2 4SW6.1
S4_PB23_SICK: 4K4.2 4R20.1
S4_PB23_SICK_1: 4J1.3 4R20.2
S4_PB24: 4C143.2 4K4.6 4R58.1 SITE4.73(UART_LOG_TXD/UART_DOWNLOAD/GPIOF_3/PB[24])
S4_PB24_1: 4R58.2 4SW6.2
S4_PB24_SIDD: 4K4.7 4R21.1
S4_PB24_SIDD_1: 4J1.4 4R21.2
S4_PB25: 4K8.3 4R59.1 SITE4.96(SPI0_CLK/SWD_CLK/SD_D2/ICFG2/GPIOG_0/PB[25])
S4_PB25_1: 4R59.2 4SW6.3
S4_PB25_I2C_SCL: 4K8.2 4R31.1
S4_PB25_I2C_SCL_1: 4J3.3 4R31.2
S4_PB26: 4K8.6 4R60.1 SITE4.97(SPI0_CS/SWD_DATA/SD_D3/ICFG3/GPIOG_1/PB[26])
S4_PB26_1: 4R60.2 4SW6.4
S4_PB26_I2C_SDA: 4K8.7 4R32.1
S4_PB26_I2C_SDA_1: 4J3.4 4R32.2
S4_RF_A: 4C13.1 4C14.1 4C15.1 4D3.1(CATHODE_D1) 4SMP3.1
S4_RF_G: 4C6.1 4C7.1 4C8.1 4D2.1(CATHODE_D1) 4SMP2.1
S4_RFIN_A: 4C16.2 4R9.1 SITE4.29(RFIN_A/GND_(<750um))
S4_RFIN_G: 4C9.2 4R5.1 SITE4.31(RFIN_G/GND)
S4_RFIO_A: 4C11.2 4R6.1 SITE4.28(RFIO_A__(<750um))
S4_RFIO_BT: 4C1.2 4R1.1 SITE4.37(RFIO_BT)
S4_RFIO_G: 4C4.2 4R2.1 SITE4.32(RFIO_G)
S4_RREF_MEM: 4K9.3 4R43.1 SITE4.60(RREF_MEM)
S4_SPI_CLK: 4K1.7 4R15.2
S4_SPI_CLK/PB28: 4K1.6 SITE4.90(SPI_FLASH_CLK/SD_CLK/GPIOG_3/PB[28])
S4_SPI_CS: 4K3.2 4R10.1
S4_SPI_CS/PC0: 4K3.3 SITE4.95(SPI_FLASH_CS/UART1_CTS/SD_CD/GPIOG_7/PC[0])
S4_SPI_D0/PB29: 4K1.3 SITE4.91(SPI_FLASH_DATA0/UART1_RXD/SD_D0/GPIOG_4/PB[29])
S4_SPI_D1/PB31: 4K3.6 SITE4.94(SPI_FLASH_DATA1/UART1_RTS/SD_WP/GPIOG_6/PB[31])
S4_SPI_D2/PB30: 4K2.6 SITE4.92(SPI_FLASH_DATA2/UART1_TXD/SD_D1/GPIOG_5/PB[30])
S4_SPI_D3/PB27: 4K2.3 SITE4.89(SPI_FLASH_DATA3/SD_CMD/GPIOG_2/PB[27])
S4_SPI_DATA0: 4K1.2 4R17.2
S4_SPI_DATA1: 4K3.7 4R11.1
S4_SPI_DATA2: 4K2.7 4R16.1
S4_SPI_DATA3: 4K2.2 4R13.2
S4_U1_VC1: 4K39.5 4U1.4(VCTL)
S4_U2_VC1: 4K39.4 4U2.4(VCTL)
S4_VA09_MIPI: 4BD37.2 4C152.1 SITE4.84(VA09_MIPI/VA09_CK/VA09_DA)
S4_VA09_PLL: 4BD1.2 4C44.1 SITE4.11(VA09_PLL/VD09_CORE0)
S4_VA09_USB: 4BD2.2 4C45.1 SITE4.77(VA09_USB)
S4_VA13_AFE: 4BD20.2 4C88.1 SITE4.19(VA13_AFE)
S4_VA13_SYN: 4BD16.2 4C78.1 SITE4.23(VR13_SYN)
S4_VA33_SYN: 4BD13.2 4C64.1 SITE4.24(VR33_SYN)
S4_VA33_XTAL: 4BD5.2 4C48.1 SITE4.20(VA33_XTAL)
S4_VD09_CORE1: 4C47.1 4R76.2 SITE4.56(VD09_CORE1/VD09MEM0)
S4_VD09_CORE2: 4C49.1 4R77.2 SITE4.64(VD09_CORE2/VD09_MEM1)
S4_VD09_CORE3: 4C54.1 4R78.2 SITE4.87(VD09_CORE3/VA09_PLL)
S4_VD09_CORE4: 4C58.1 4R79.2 SITE4.98(VD09_CORE4)
S4_VD13_FE: 4BD19.2 4C85.1 SITE4.36(VD13_FE)
S4_VD13_RF: 4BD17.2 4C79.1 SITE4.25(VD13_RF)
S4_VD33_ALL: 4BD3.1 4BD5.1 4BD7.1 4BD9.1 4BD11.1 4BD12.1 4BD13.1 4BD15.1 4BD18.1 4BD21.1 4BD22.1 4BD23.1 4BD28.1 4BD29.1 4BD30.1 4BD31.1 4BD32.1 4BD36.1 4C67.1 4C96.1 4C101.1 4C122.1 4C129.1 4J5.1 4J6.1 4K23.2 4K23.7
S4_VD33_CM_BT: 4BD21.2 4C90.1 4C91.1 SITE4.35(VD33_CM_BT)
S4_VD33_EX_FLASH: 4BD32.2 4C22.1 4C127.1 4C128.1 4R12.2 4R14.1 4U3.8(VCC)
S4_VD33_IO0: 4BD7.2 4C52.1 SITE4.9(VA33_PLL/VD33_IO0)
S4_VD33_IO2: 4BD9.2 4C56.1 SITE4.59(VD33_IO2/VD33_MEM)
S4_VD33_IO3: 4BD11.2 4C59.1 SITE4.70(VD33_IO3/VDD_IO4/VA33_USB)
S4_VD33_IO6: 4BD12.2 4C61.1 SITE4.88(VD33_IO6/VDD33_IO5/VD33_FLASH)
S4_VD33_SPS_AUD: 4BD30.2 4C123.1 4C124.1 SITE4.1(VD33_SPS_AUD)
S4_VD33_SPS_DCORE: 4BD28.2 4C111.1 4C112.1 SITE4.2(VD33_SPS_DCORE)
S4_VD33_SPS_MEM: 4BD31.2 4C125.1 4C126.1 SITE4.76(VD33_SPS_MEM)
S4_VD33PA_A: 4BD23.2 4C99.1 4C100.1 SITE4.27(VD33PA_A)
S4_VD33PA_BT: 4BD18.2 4C83.1 4C84.1 SITE4.38(VD33PA_BT)
S4_VD33PA_G: 4BD15.2 4C76.1 4C77.1 SITE4.33(VD33PA_G)
S4_VD33PAD_A: 4BD22.2 4C97.1 4C98.1 SITE4.26(VD33PAD_A)
S4_VD33PAD_G: 4BD36.2 4C73.1 4C74.1 SITE4.34(VD33PAD_G)
S4_VD1833_IO1: 4BD3.2 4C46.1 SITE4.14(VD1833_IO1)
S4_VD1833_SDIO: 4BD29.2 4C118.1 4C119.1 SITE4.93(VD1833_SDIO)
S4_VD_MEM0: 4C102.1 4R81.2 SITE4.61(VD_MEM0)
S4_VD_MEM1: 4C105.1 4R82.2 SITE4.62(VD_MEM1)
S4_VD_MEM2: 4C107.1 4R83.2 SITE4.65(VD_MEM2)
S4_VDD09: 4K22.2 4K22.5 4K31.4 4R48.1 S4_VDD09.1(TP)
S4_VDD09_CH: 4K37.4 4ST13.1
S4_VDD18_A: 4K25.2 4K25.5 4K26.3 4K32.4 4R55.1 S4_VDD18_A.1(TP)
S4_VDD18_D: 4K28.2 4K28.5 4K30.4 4R29.2 4R53.1 S4_VDD18_D.1(TP)
S4_VDD33: 4BD33.2 4C130.1 4R19.1 4R24.1 4R30.1 4R38.2 4R61.2 4U1.6(VDD) 4U2.6(VDD)
S4_VDD33_J1: 4J1.1 4R19.2
S4_VDD33_J2: 4J2.1 4R24.2
S4_VDD33_J3: 4J3.1 4R30.2
S4_VREF_DRAM: 4C153.1 4K16.3 SITE4.63(VREF_DRAM/NC(PSRAM))
S4_XI: 4C25.2 4Y1.1 SITE4.22(XI)
S4_XO: 4C23.2 4Y1.3 SITE4.21(XO)
S5_LPC_009: 4K38.6
S5_LPC_012: 4K37.6
S5_LPC_043: 4K33.6
S5_LX_AUD_CH_1: 4K38.7 ; also on sheet 19
S5_LX_AUD_CH_2: 4K38.5 ; also on sheet 19
S5_LX_DCORE_CH: 4K37.7 ; also on sheet 19
S5_LX_MEM_CH_1: 4K33.7 ; also on sheet 19
S5_LX_MEM_CH_2: 4K33.5 ; also on sheet 19
S5_VDD09_CH: 4K37.5 ; also on sheet 19
S4567_CBIT_001: 4K7.9(V-) 4SW1.7 ; also on sheet 17 20 23
S4567_CBIT_002: 4K37.8(V-) 4SW7.2 ; also on sheet 22
S4567_CBIT_003: 4K6.8(V-) 4SW1.6 ; also on sheet 17 20 23
S4567_CBIT_004: 4K2.8(V-) 4SW1.2 ; also on sheet 17 20 23
S4567_CBIT_005: 4K3.8(V-) 4SW1.3 ; also on sheet 17 20 23
S4567_CBIT_006: 4K35.8(V-) 4SW4.8 ; also on sheet 18 21 24
S4567_CBIT_007: 4K33.8(V-) 4SW4.6 ; also on sheet 22
S4567_CBIT_008: 4K30.8(V-) 4SW4.3 ; also on sheet 19 22 25
S4567_CBIT_009: 4K32.8(V-) 4SW4.5 ; also on sheet 19 22 25
S4567_CBIT_010: 4K31.8(V-) 4SW4.4 ; also on sheet 19 22 25
S4567_CBIT_011: 4K29.8(V-) 4SW4.2 ; also on sheet 19 22 25
S4567_CBIT_012: 4K28.8(V-) 4SW4.1 ; also on sheet 19 22 25
S4567_CBIT_013: 4K8.8(V-) 4SW1.8 ; also on sheet 17 20 23
S4567_CBIT_014: 4K26.8(V-) 4SW3.8 ; also on sheet 19 22 25
S4567_CBIT_015: 4K34.8(V-) 4SW4.7 ; also on sheet 18 21 24
S4567_CBIT_016: 4K16.8(V-) 4SW2.8 ; also on sheet 17 20 23
S4567_CBIT_017: 4K21.8(V-) 4SW3.4 ; also on sheet 19 22 25
S4567_CBIT_018: 4K18.8(V-) 4SW3.1 ; also on sheet 18 21 24
S4567_CBIT_019: 4K22.8(V-) 4SW3.5 ; also on sheet 19 22 25
S4567_CBIT_020: 4K9.8(V-) 4SW2.1 ; also on sheet 17 20 23
S4567_CBIT_022: 4K19.8(V-) 4SW3.2 ; also on sheet 18 21 24
S4567_CBIT_023: 4K23.8(V-) 4SW3.6 ; also on sheet 19 22 25
S4567_CBIT_024: 4K20.8(V-) 4SW3.3 ; also on sheet 19 22 25
S4567_CBIT_025: 4K13.8(V-) 4SW2.5 ; also on sheet 18 21 24
S4567_CBIT_026: 4K14.8(V-) 4SW2.6 ; also on sheet 18 21 24
S4567_CBIT_027: 4K15.8(V-) 4SW2.7 ; also on sheet 18 21 24
S4567_CBIT_028: 4K25.8(V-) 4SW3.7 ; also on sheet 19 22 25
S4567_CBIT_029: 4K10.8(V-) 4SW2.2 ; also on sheet 18 21 24
S4567_CBIT_030: 4K11.8(V-) 4SW2.3 ; also on sheet 18 21 24
S4567_CBIT_031: 4K12.8(V-) 4SW2.4 ; also on sheet 18 21 24
S4567_CBIT_032: 4K39.8(V-) 4SW7.4 ; also on sheet 17 20 23
S4567_CBIT_033: 4K1.8(V-) 4SW1.1 ; also on sheet 17 20 23
S4567_CBIT_034: 4K38.8(V-) 4SW7.3 ; also on sheet 22
S4567_CBIT_035: 4K5.9(V-) 4SW1.5 ; also on sheet 17 20 23
S4567_CBIT_036: 4K36.8(V-) 4SW7.1 ; also on sheet 18 21 24
S4567_CBIT_037: 4K4.8(V-) 4SW1.4 ; also on sheet 17 20 23
VP12: 4K1.1(V+) 4K2.1(V+) 4K3.1(V+) 4K4.1(V+) 4K5.1(V+) 4K6.1(V+) 4K7.1(V+) 4K8.1(V+) 4K9.1(V+) 4K10.1(V+) 4K11.1(V+) 4K12.1(V+) 4K13.1(V+) 4K14.1(V+) 4K15.1(V+) 4K16.1(V+) 4K18.1(V+) 4K19.1(V+) 4K20.1(V+) 4K21.1(V+) 4K22.1(V+) 4K23.1(V+) 4K25.1(V+) 4K26.1(V+) 4K28.1(V+) 4K29.1(V+) 4K30.1(V+) 4K31.1(V+) 4K32.1(V+) 4K33.1(V+) 4K34.1(V+) 4K35.1(V+) 4K36.1(V+) 4K37.1(V+) 4K38.1(V+) 4K39.1(V+) ; also on sheet 2 3 4 5 6 7 8 9 10 11 12 13 17 18 19 20 21 22 23 24 25 26 27 29 38
N27466443: 4C10.1 4R5.2 4U1.3(RF2)
N27466449: 4C7.2 4U1.5(ANT)
N27466452: 4R4.1 4U1.1(RF1)
N27466503: 4C6.2 4R3.2
N27466512: 4C19.1 4R9.2 4U2.1(RF1)
N27466519: 4C14.2 4U2.5(ANT)
N27466526: 4C12.1 4R6.2 4R7.1 4R8.2
N27466528: 4C13.2 4R7.2
N27466547: 4BD27.2 4C24.1 4K16.4
N27466557: 4K5.6 4R22.1
N27466559: 4K5.4 4R25.1
N27466562: 4R8.1 4U2.3(RF2)
N27466568: 4C5.1 4R2.2 4R3.1 4R4.2
N27466596: 4C2.1 4C3.1 4R1.2
N27466601: 4C2.2 4D1.1(CATHODE_D1) 4SMP1.1
N27466719: 4K7.6 4R23.1
N27466720: 4K7.4 4R26.1
N27466725: 4BD27.1 4R29.1 4R33.2
N27466852: 4C20.1 SITE4.47(VREF_AUDIO)
N27470451: 4K18.2 4K19.3
N27470452: 4K18.7 4K19.6
N27470455: 4C39.1 4K19.4
N27470456: 4C38.2 4K19.2
N27470459: 4C41.1 4K19.5
N27470460: 4C40.2 4K19.7
N27470491: 4R47.2 4R74.2
N27470573: 4R45.2 4R75.2
N27470589: 4C145.2 4K34.4
N27470590: 4C146.2 4K34.5
N27470597: 4C147.2 4K35.4
N27470598: 4C148.2 4K35.5
N27470601: 4C149.2 4K36.4
N27470602: 4C150.2 4K36.5
N27471689: 4K21.2 4L1.1
N27471719: 4K29.2 4L3.1
N27471720: 4C106.1 4C108.1 4C109.1 4K28.3 4L3.2
N27471731: 4K28.4 4R54.1
N27471735: 4C116.1 4C117.1 4K28.6 4K29.5
N27471758: 4C53.1 4C55.1 4C57.1 4K22.3 4L1.2
N27471770: 4K22.4 4R49.1
N27471774: 4C62.1 4C63.1 4K21.5 4K22.6
N27471889: 4K20.2 4L4.1
N27471890: 4C136.1 4C137.1 4C138.1 4K25.3 4L4.2
N27471901: 4K25.4 4R51.1
N27471903: 4C139.1 4C142.1 4K20.5 4K25.6
N27472009: 4K30.3 4R71.1
N27472011: 4K31.3 4R72.1
N27472013: 4K32.3 4R73.1
N27683469: 4R61.1 4SW6.6
N27683473: 4R62.1 4SW6.5
N27683595: 4R38.1 4SW5.10
N27683599: 4R42.1 4SW5.9

Not connected (* = marked no-connect by the designer): 4K7 3* 7*; 4K9 2* 5* 6* 7*; 4K16 5* 6* 7*; 4K20 7*; 4K21 7*; 4K22 7*; 4K23 4* 5*; 4K25 7*; 4K26 4* 7*; 4K28 7*; 4K29 7*; 4K30 2* 5* 6* 7*; 4K31 2* 5* 6* 7*; 4K32 2* 5* 6* 7*; 4SW5 8*; 4SW7 5* 6* 7* 8*; SITE4 GH1* GH2* GH3* GH4* NUT1* NUT2* NUT3* NUT4*

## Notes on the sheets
sheet 14
- WIFI/BT_RF
- place by Z-shape
- R3 and R4 Share PAD,
  Default R3
- C6 and C7 Share PAD,
  Default C6
- place by Z-shape
- place by Z-shape
- R7 and R8 Share PAD,
  Default R7
- C13 and C14 Share PAD,
  Default C13
- place by Z-shape
- place by Z-shape
- GND Shielding
- FLASH
- RF SW Channel  and PA9.10 share one Channel
- GND Shielding
- Mark On Board
- GND Shielding
- Debug
- Mark On  Board
- 1.S0_VDD33
- PIN1->4K1,5K1,6K1,7K1
- 2.GND
- PIN2->4K2,5K2,6K2,7K2
- 3.S0_SICK
- PIN3->4K3,5K3,6K3,7K3
- DSSC
- 4.S0_SIDD
- PIN4->4K4,5K4,6K4,7K4
- PIN5->4K5,5K5,6K5,7K5
- SIC
- PIN6->4K6,5K6,6K6,7K6
- USB
- GND Shielding
- PIN7->4K7,5K7,6K7,7K7
- PIN8->4K8,5K8,6K8,7K8
- Mark On Board
- Mark On Board
- Debug
- 1.S0_VDD33
- PIN1->4K9,5K9,6K9,7K9
- PIN2->4K10,5K10,6K10,7K10
- 2.GND
- PIN3->4K11,5K11,6K11,7K11
- 3.S0_UART_RX
- PIN4->4K12,5K12,6K12,7K12
- 4.S0_UART_TX
- PIN5->4K13,5K13,6K13,7K13
- PIN6->4K14,5K14,6K14,7K14
- DIFF 90ohm
- UART
- PIN7->4K15,5K15,6K15,7K15
- DIFF 90ohm
- PIN8->4K16,5K16,6K16,7K16
- Mark On Board
- Debug
- Mark On Board
- PIN1->4K18,5K18,6K18,7K18
- XTAL
- VREF_DRAM
- PIN2->4K19,5K19,6K19,7K19
- PIN3->4K20,5K20,6K20,7K20
- GND Shielding
- 1.S0_VDD33
- PIN4->4K21,5K21,6K21,7K21
- Close To DUT
- 2.GND
- PIN5->4K22,5K22,6K22,7K22
- 3.S0_I2C_SCL
- PIN6->4K23,5K23,6K23,7K23
- DSSC
- 4.S0_I2C_SDA
- PIN7->4K25,5K25,6K25,7K25
- PIN8->4K26,5K26,6K26,7K26
- BT_I2C
- GND Shielding
- Mark On Board
- Mark On Board
- PIN1->4K28,5K28,6K28,7K28
- 1.S0_CHIP_EN
- PIN2->4K29,5K29,6K29,7K29
- 2.S0_PB22_TEST_MODE_SEL
- PIN3->4K30,5K30,6K30,7K30
- PIN4->4K31,5K31,6K31,7K31
- 3.S0_PB21_BOOT_SEL_FLASH
- PIN5->4K32,5K32,6K32,7K32
- 4.S0_PB10/ICFG0
- PIN6->4K33,6K33
- 5.S0_PB11/ICFG1
- 6.S0_PA15/ICFG2
- PIN7->4K34,5K34,6K34,7K34
- 7.S0_PA16/ICFG3
- PIN8->4K35,5K35,6K35,7K35
- 8.NC
- RREF
- Mark On Board
- PIN1->4K36,5K36,6K36,7K36
- PIN2->4K37,6K37
- PIN3->4K38,6K38
- PIN4->4K39,5K39,6K39,7K39
- Close To DUT
- Close to Relay
sheet 15
- AUDIO ADC Test
- MIPI Test
- GND Shielding
- GND Shielding
- CAP TOUCH Test
- GND Shielding
sheet 16
- CLOSE TO DUT
- POWER_VD09
- POWER_VD1833
- CLOSE TO DUT
- 110mA
- 5mA
- 33mA
- C48 TOP
- 20mA
- 102mA
- RELAY 2 SITE share
- 35mA
- 105mA
- 35mA
- 112mA
- 25mA
- 50mA
- Mark On Board : S0_VDD09
- C58 TOP
- 30mA
- 50mA
- 10mA
- C64 TOP
- 200mA
- CLOSE TO DUT
- 200mA
- POWER_VD18_AUD
- CLOSE TO DUT
- Mark On Board : S0_VDD18_A
- 200mA
- 100mA
- C75 TOP
- 50mA
- Mark On Board : S0_VDD33
- CLOSE TO DUT
- CLOSE TO DUT
- 45mA
- 60mA
- C78 TOP
- 80mA
- C79 TOP
- 45mA
- C97,C98 TOP
- RELAY 2 SITE share
- 300mA
- 25mA
- C88 TOP
- C99,C100 TOP
- POWER_VD18_DDR
- RELAY 2 SITE share
- CLOSE TO DUT
- CLOSE TO DUT
- 155mA
- 62mA
- C111,C112 TOP
- 62mA
- 30mA
- 62mA
- Mark On Board : S0_VDD18_D
- C107 TOP
- 107mA
- C123,C124 TOP
- 160mA
- C125,C126 TOP
- 50mA
- Calibration Loading SCH
